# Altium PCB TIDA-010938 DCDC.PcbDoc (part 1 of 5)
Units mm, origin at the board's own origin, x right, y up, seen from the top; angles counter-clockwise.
Board outline 275 x 165 mm, 4 copper layers (Top Layer, Layer 1, Layer 2, Bottom Layer), stack 1.787 mm thick; 436 components, 216 nets, 1367 pads, 1992 vias.
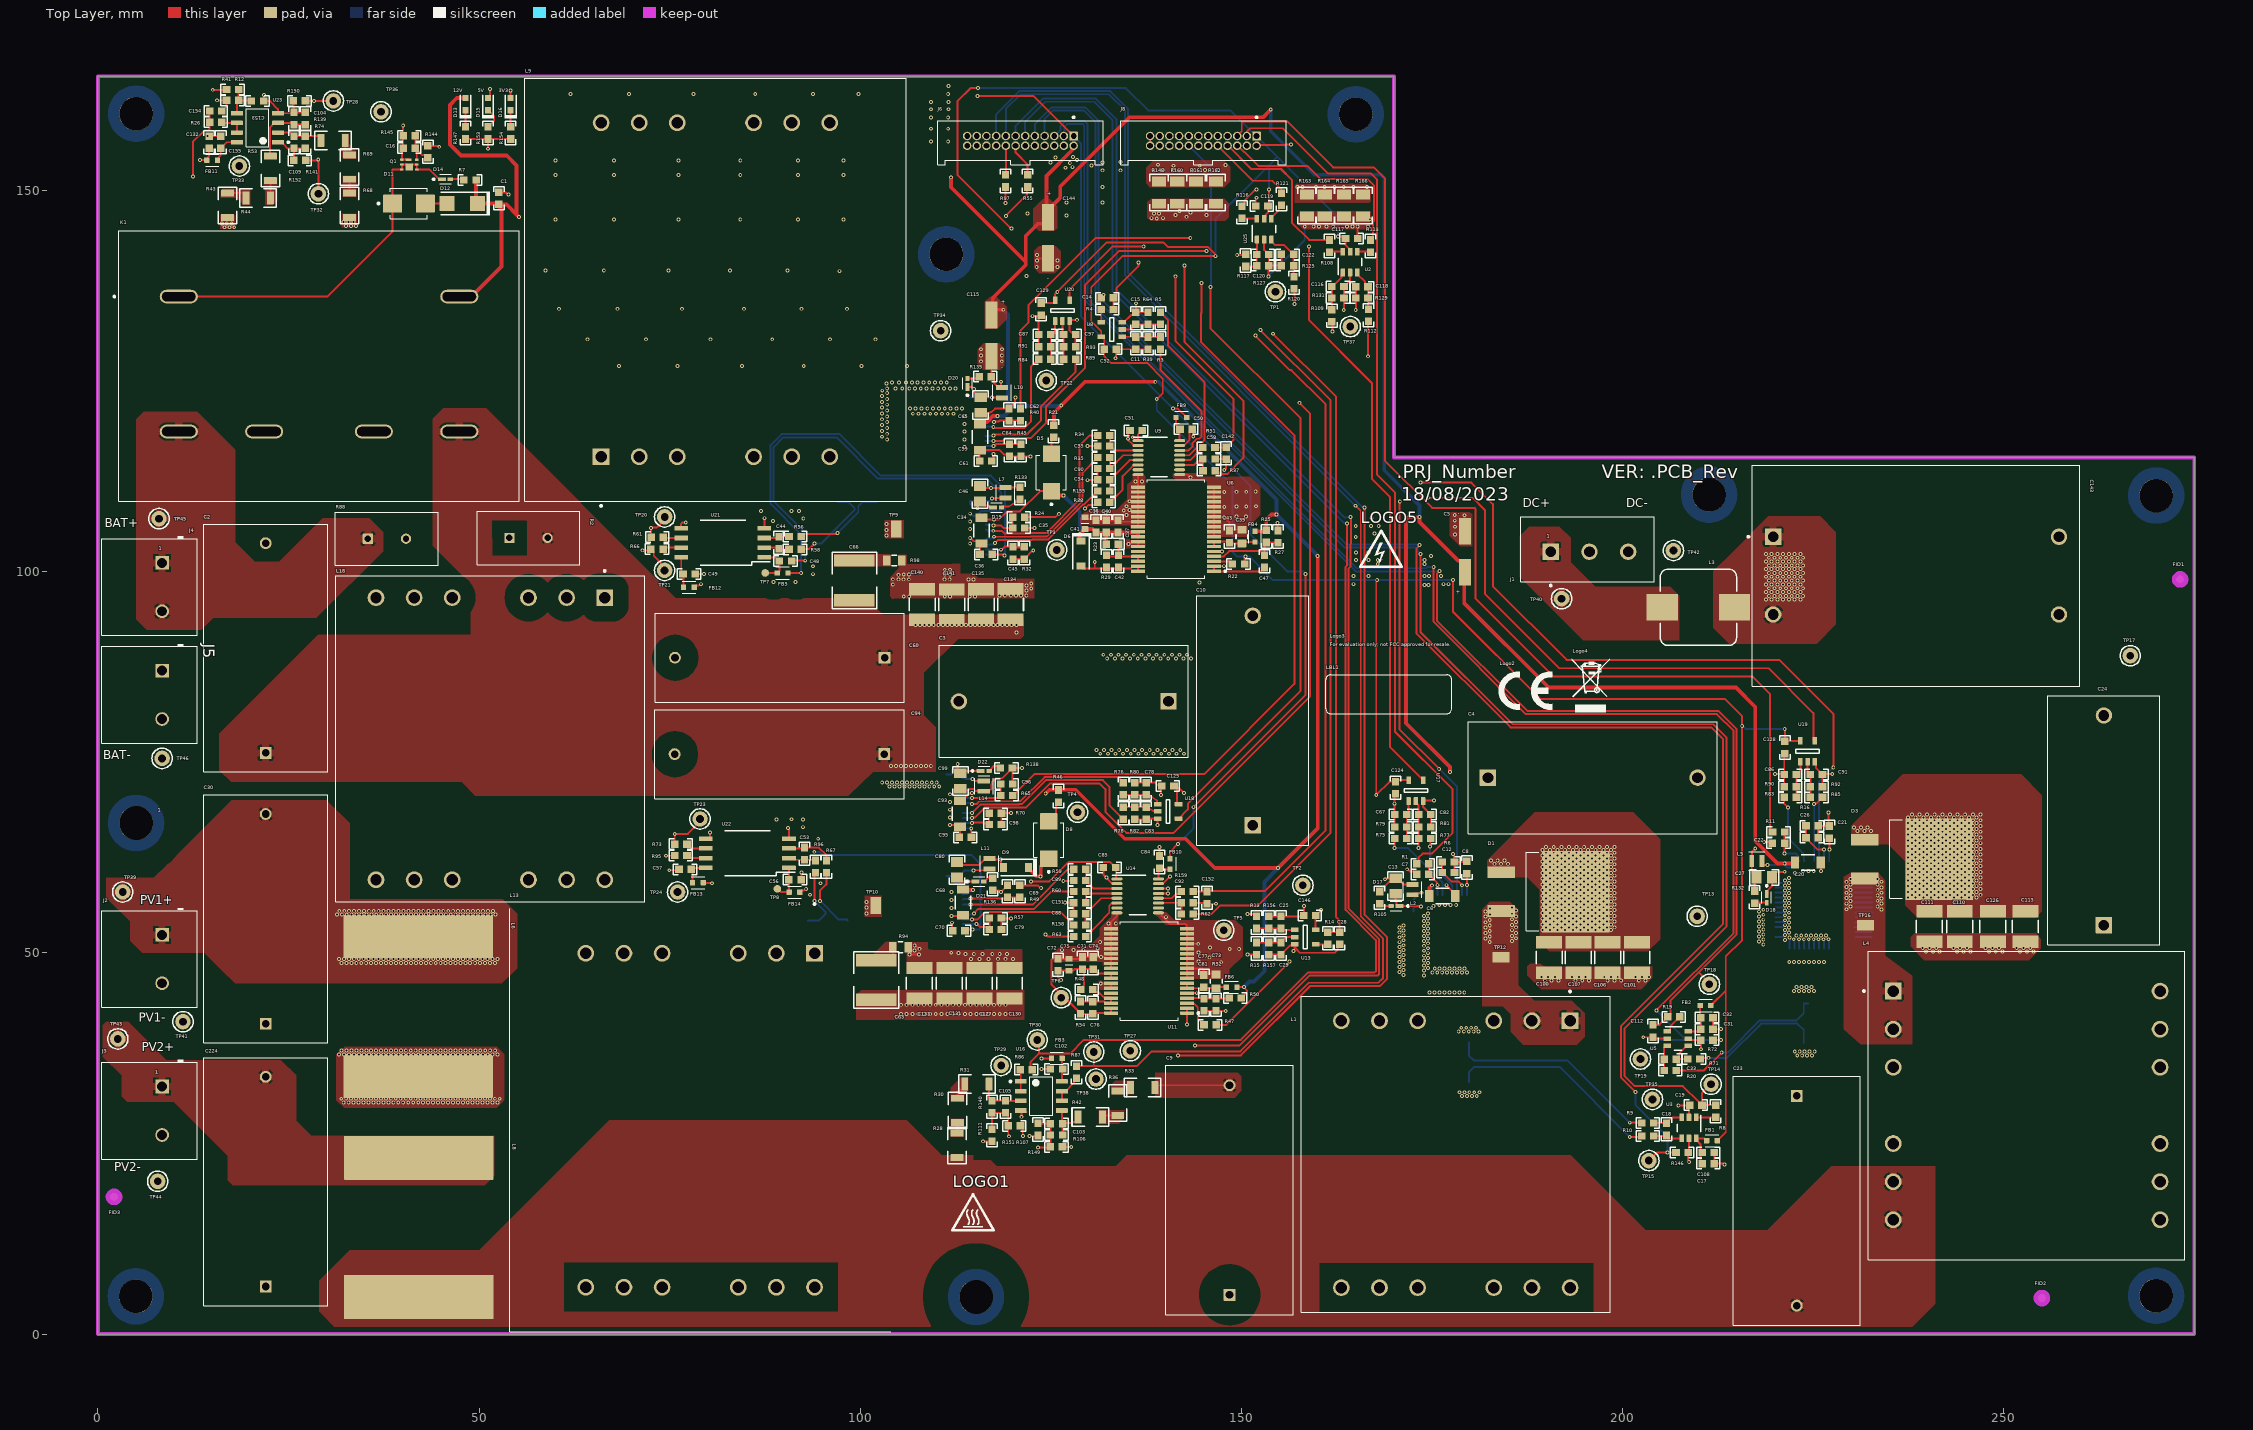
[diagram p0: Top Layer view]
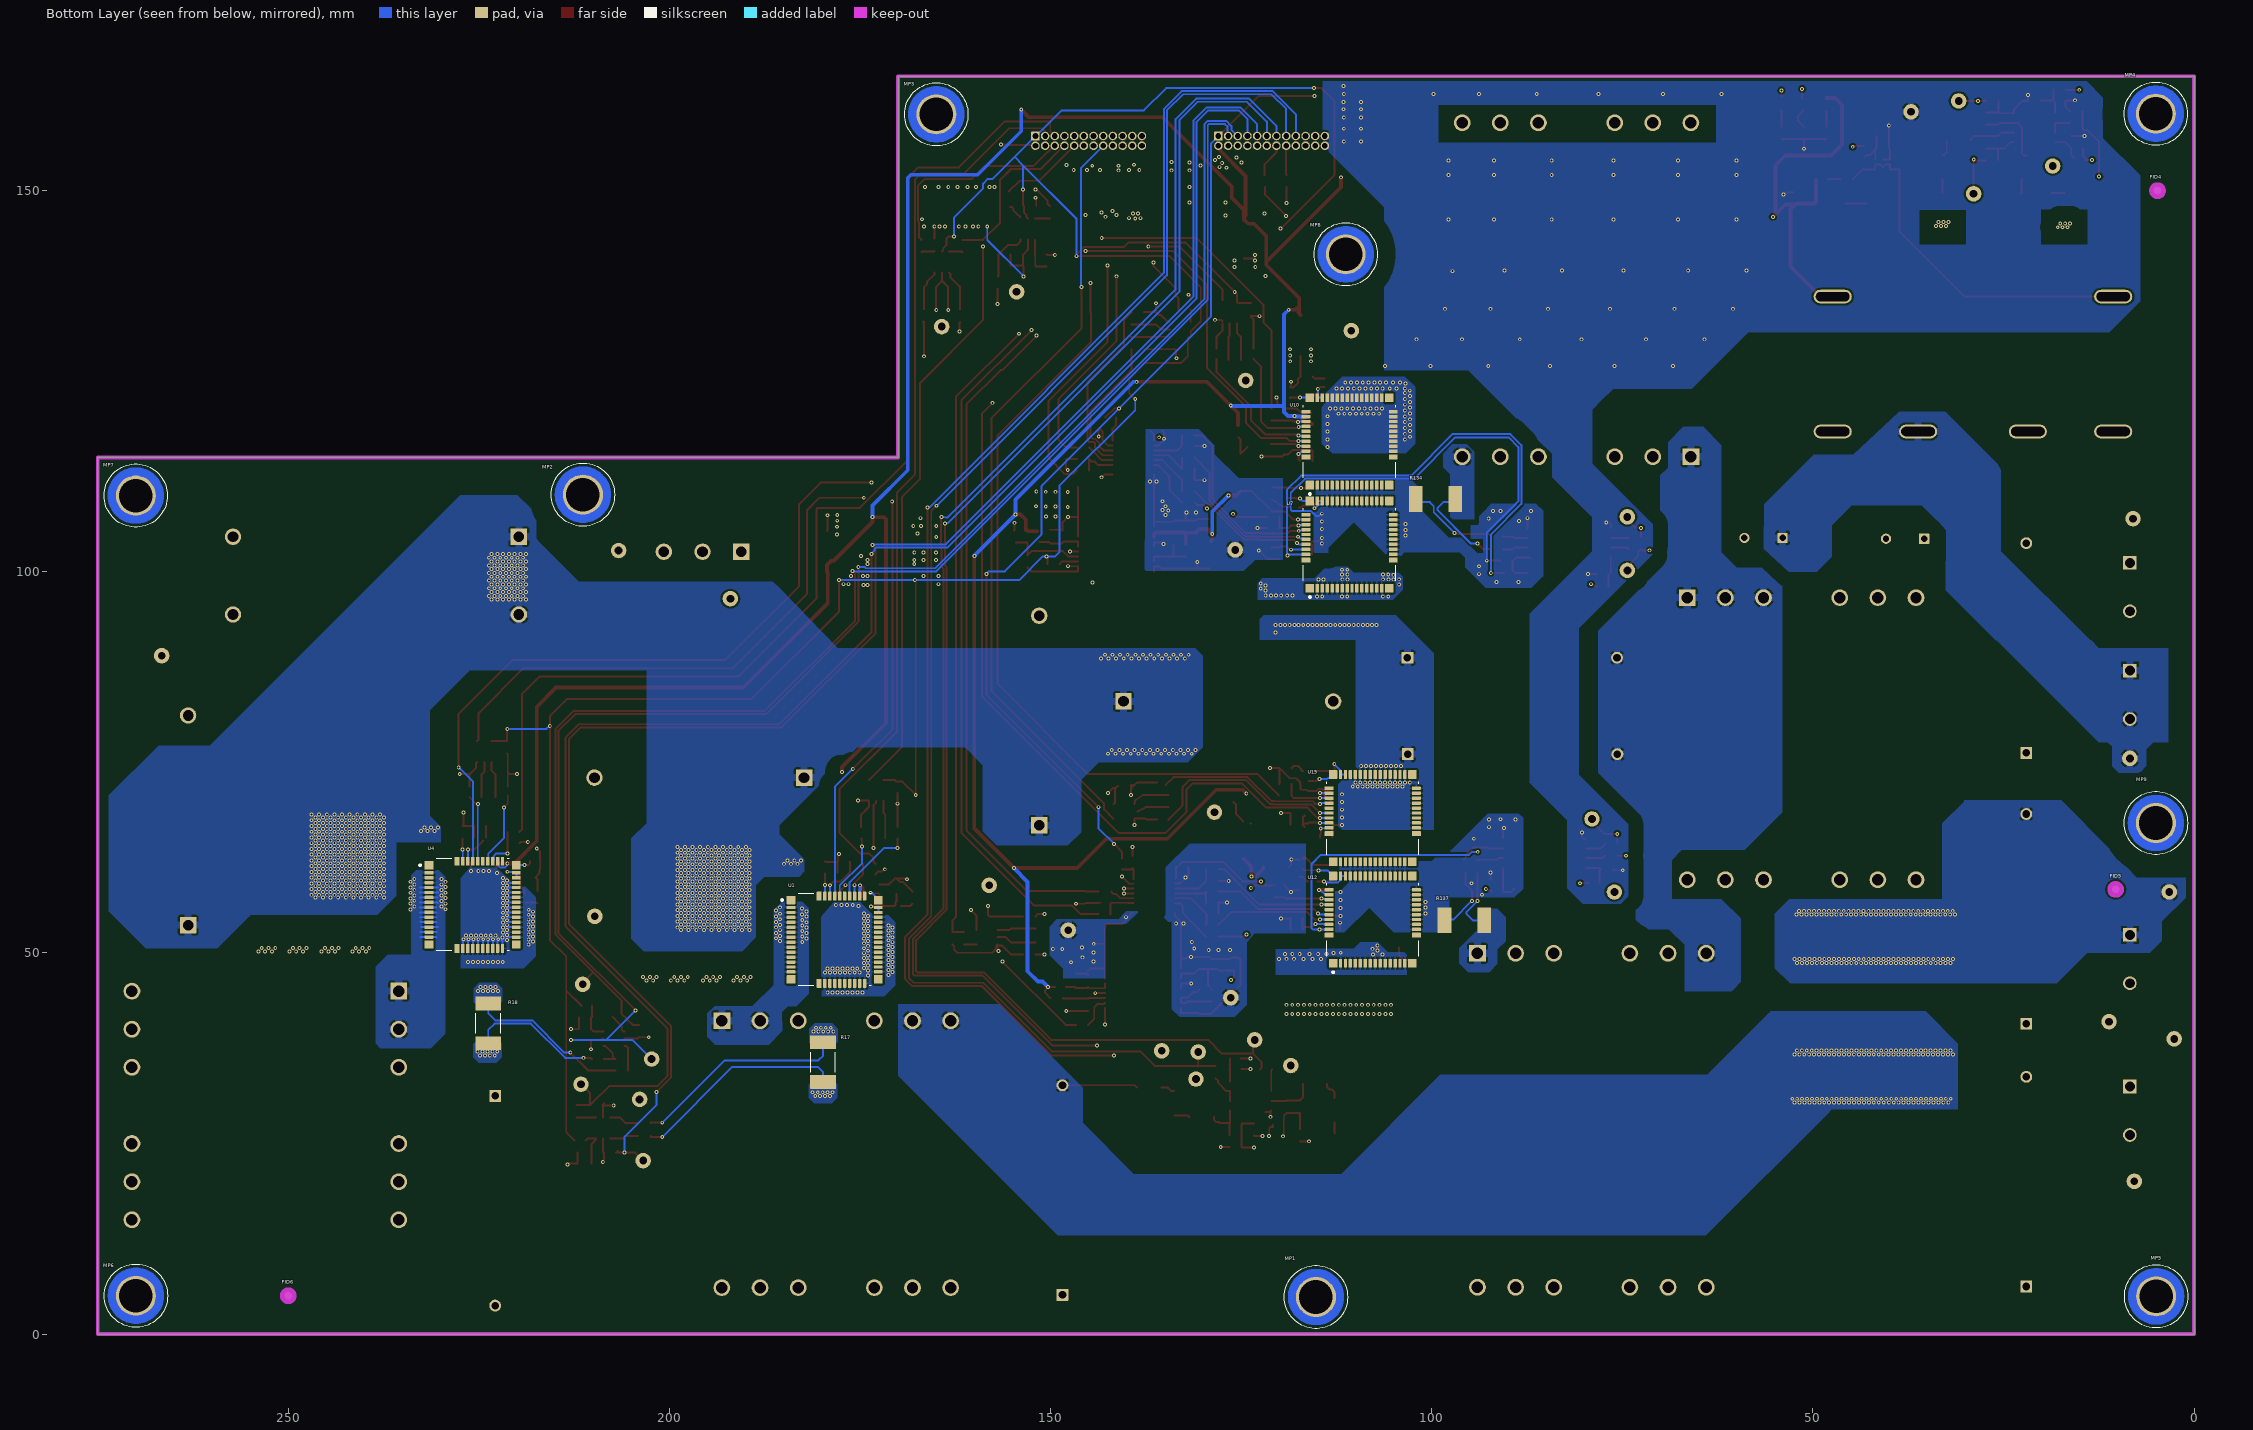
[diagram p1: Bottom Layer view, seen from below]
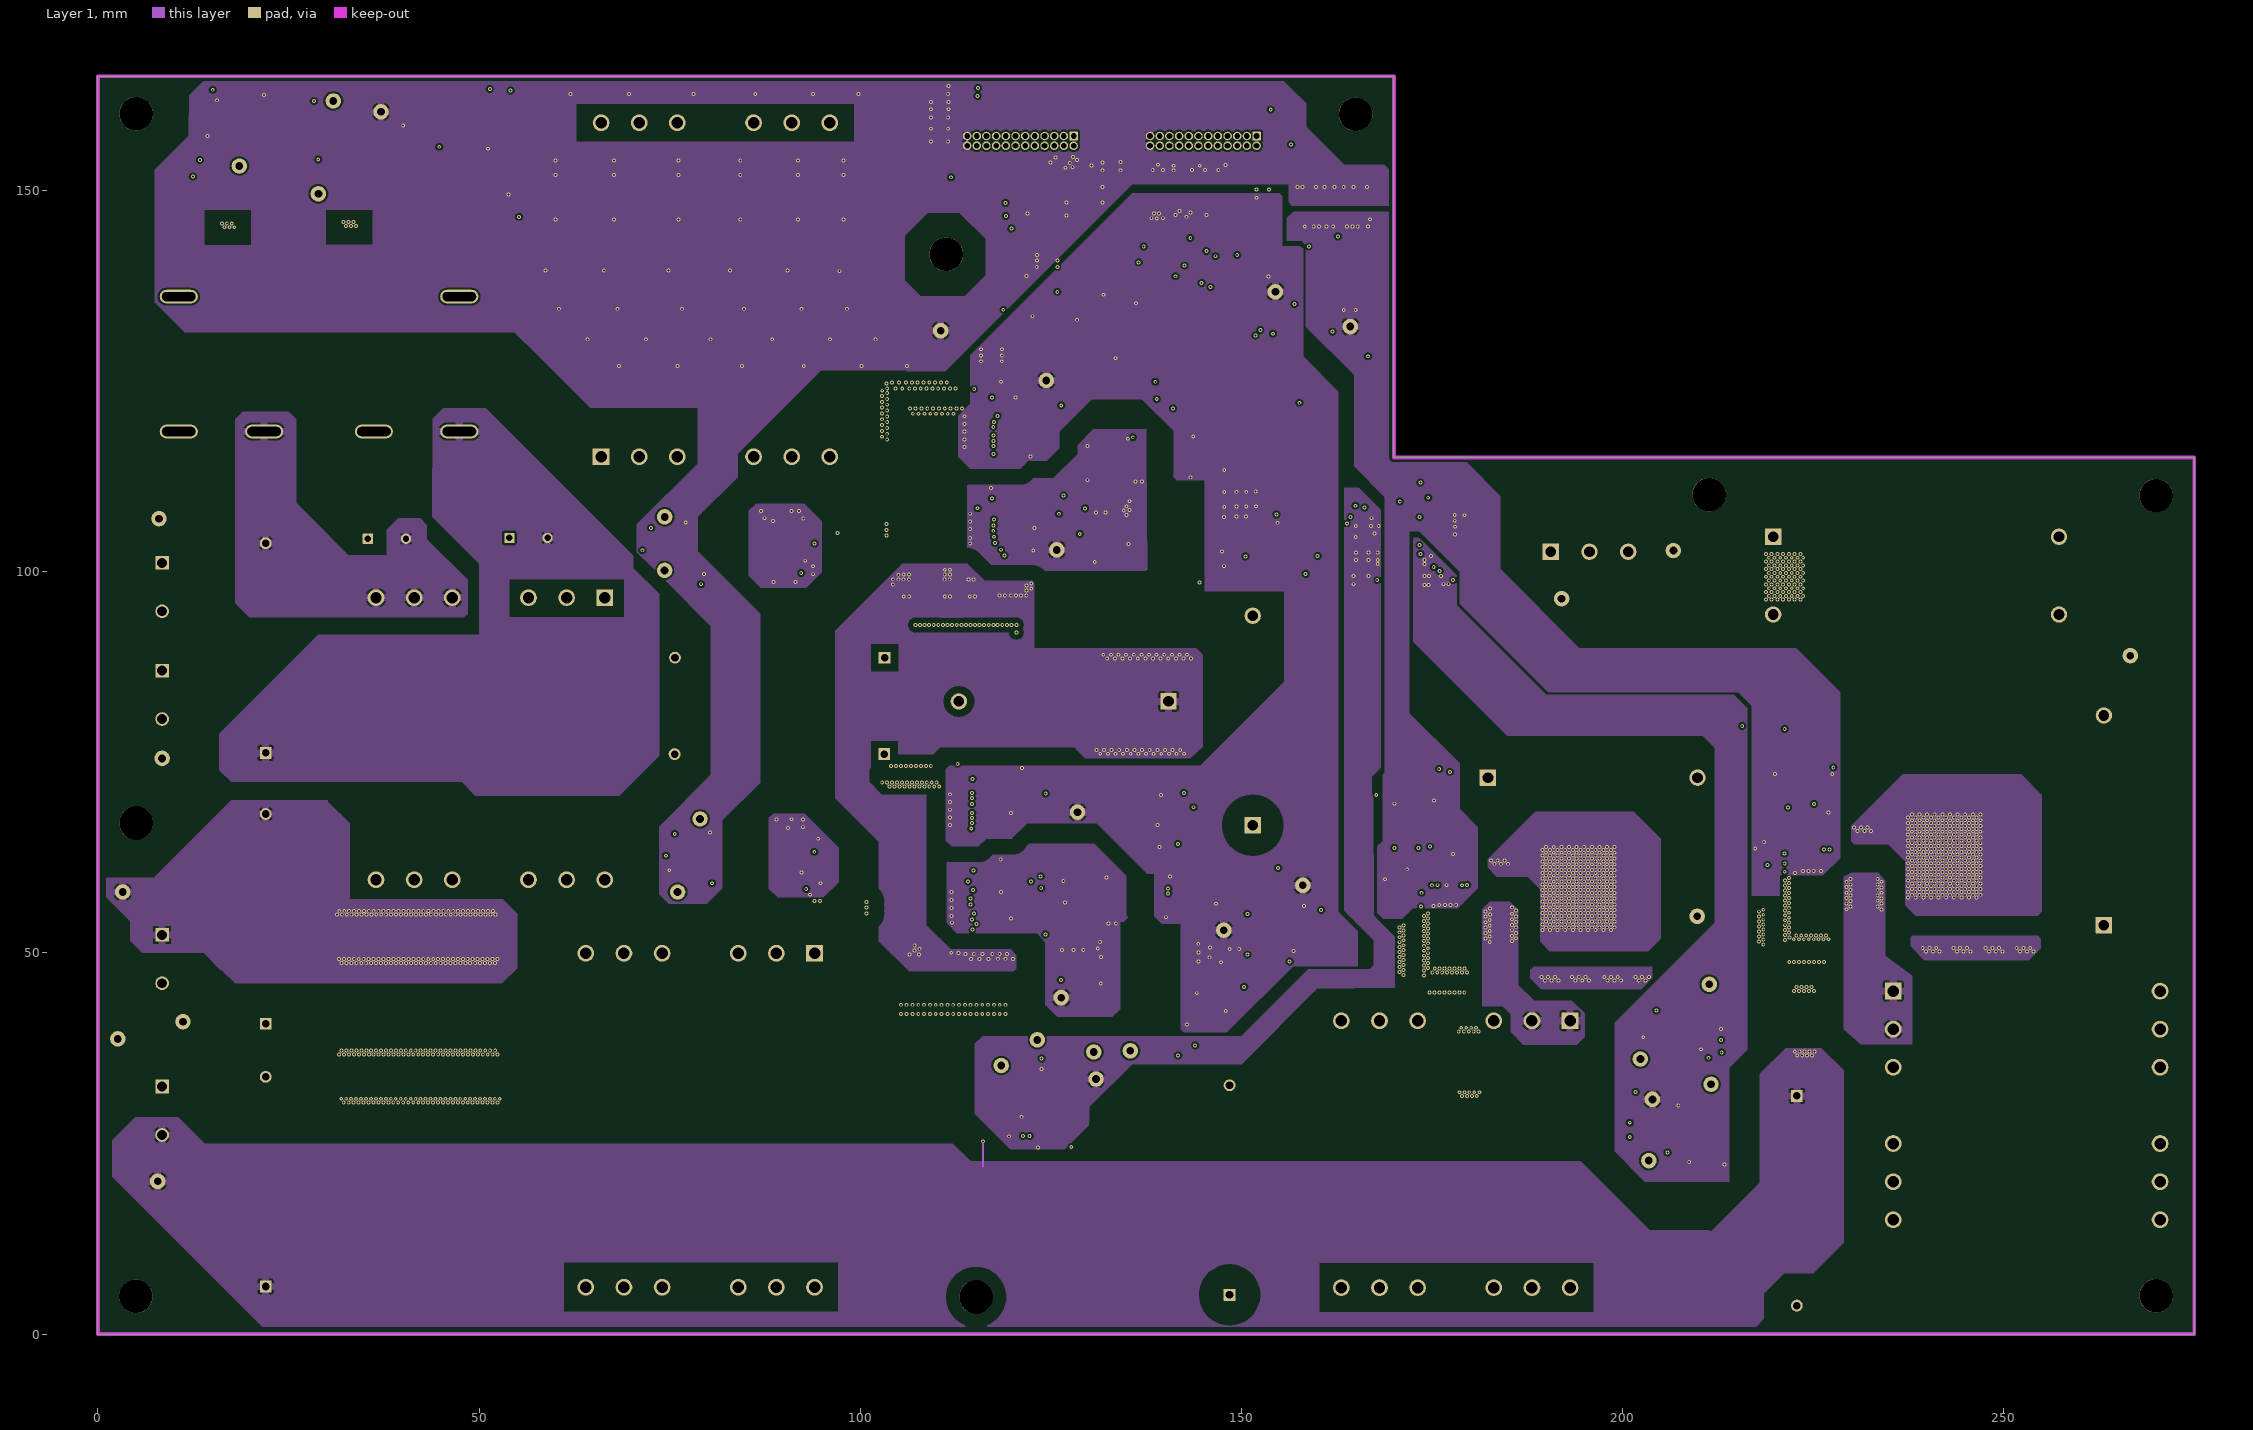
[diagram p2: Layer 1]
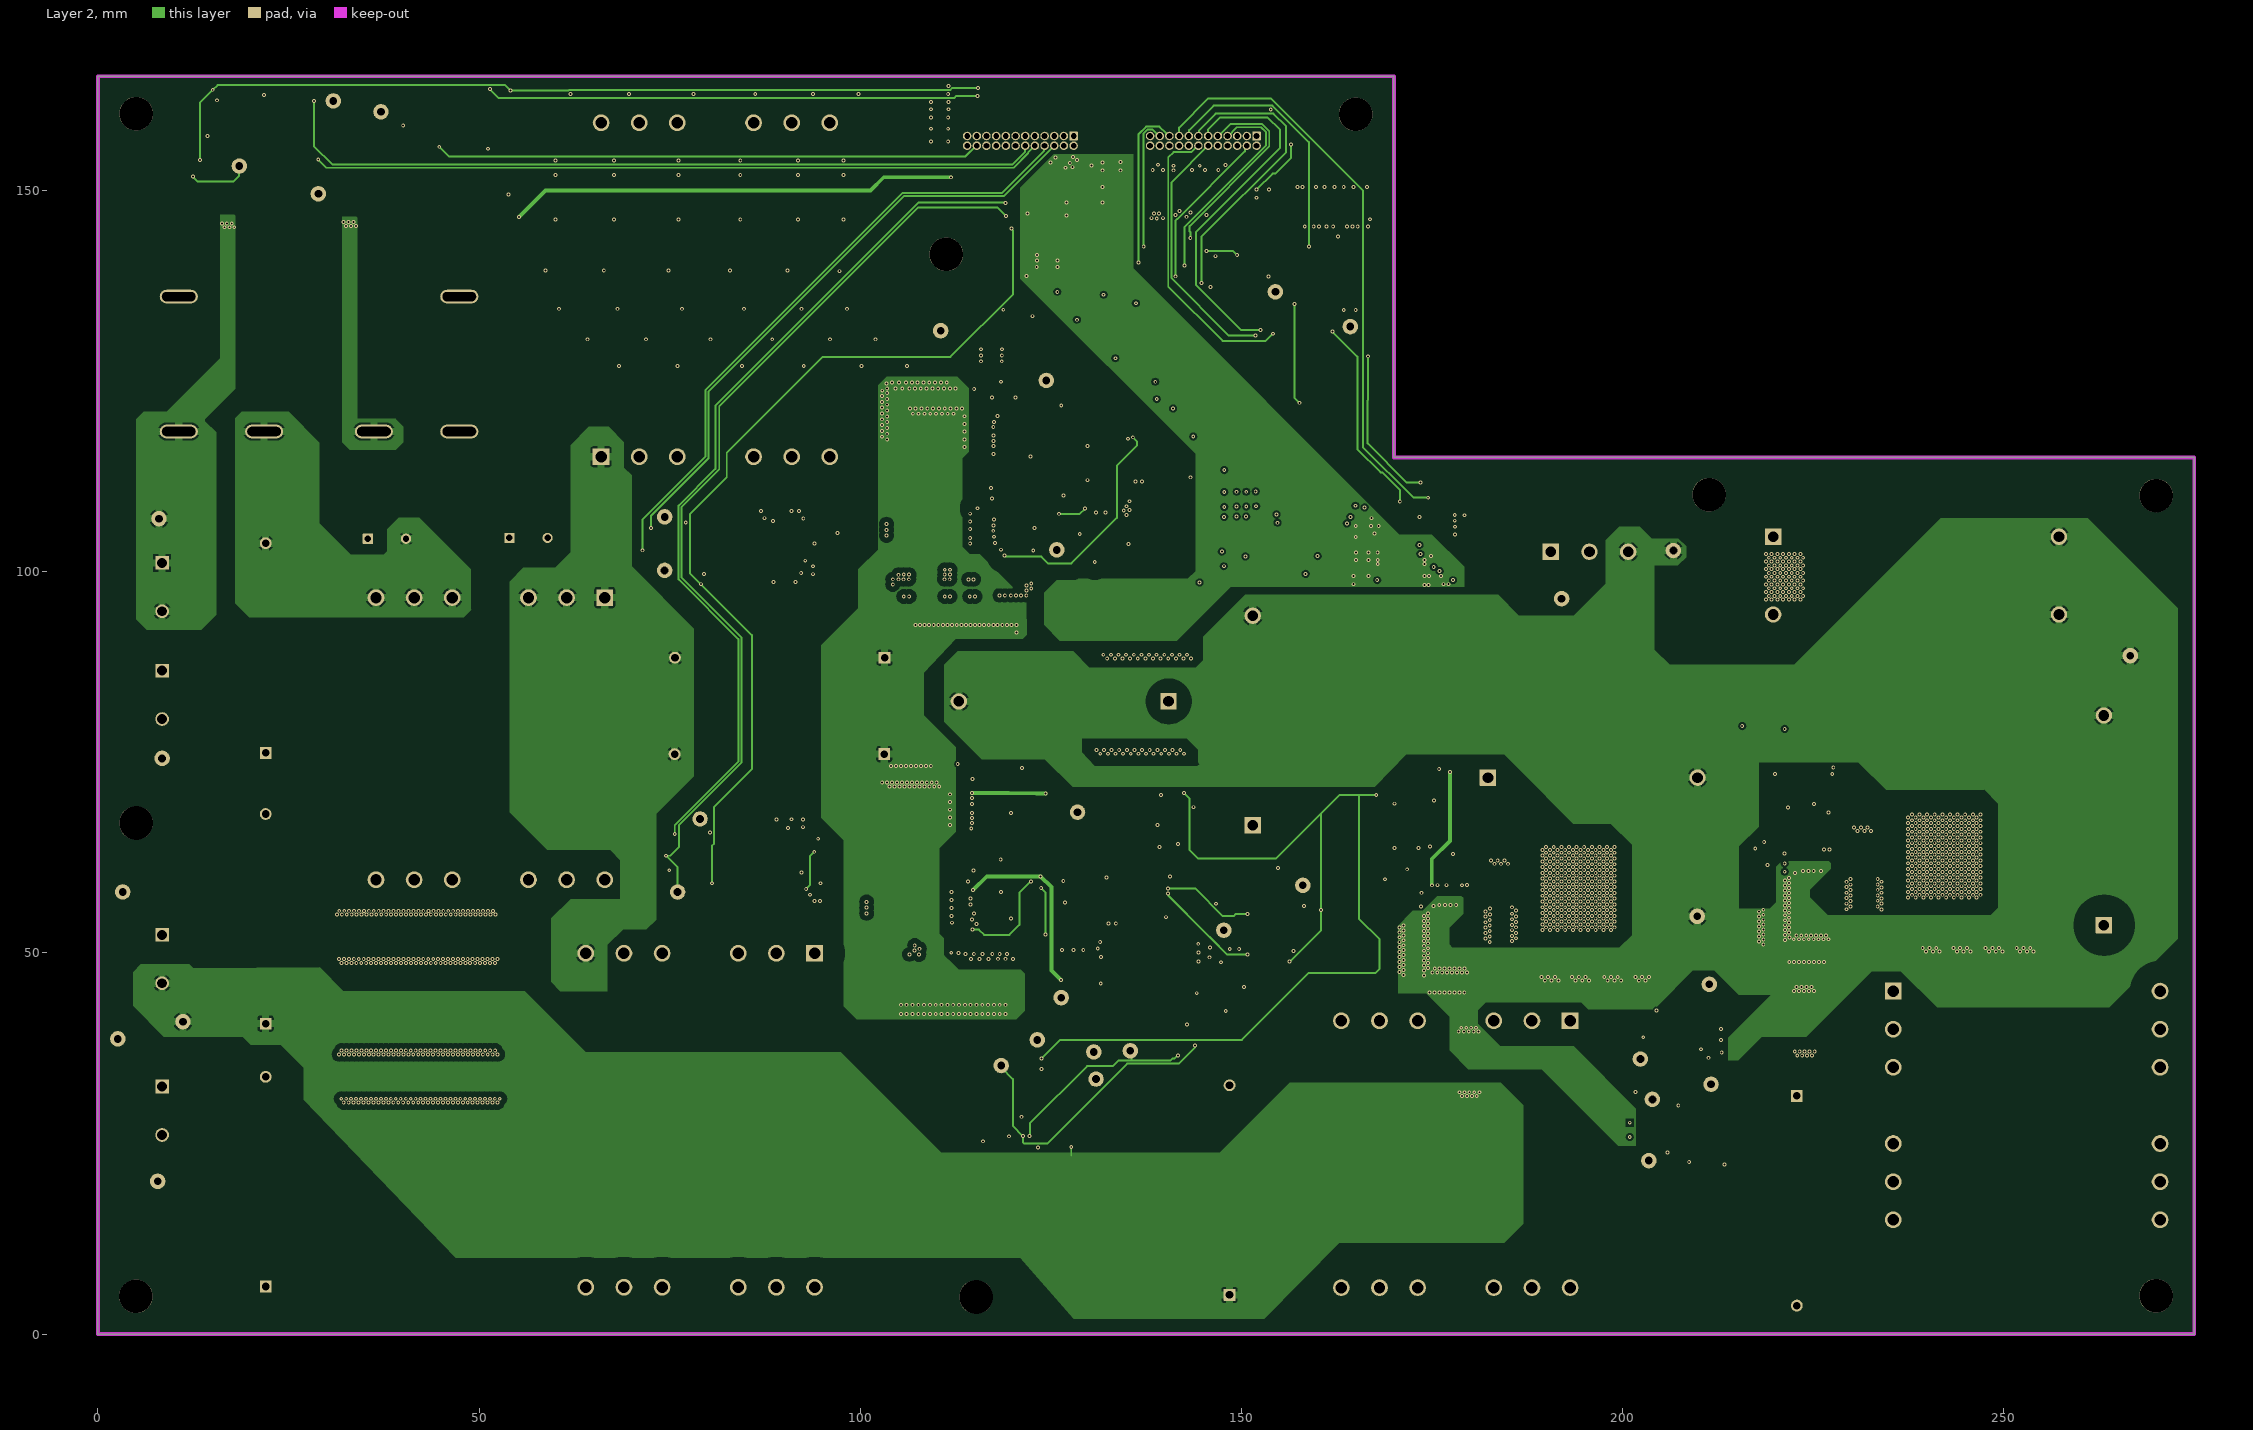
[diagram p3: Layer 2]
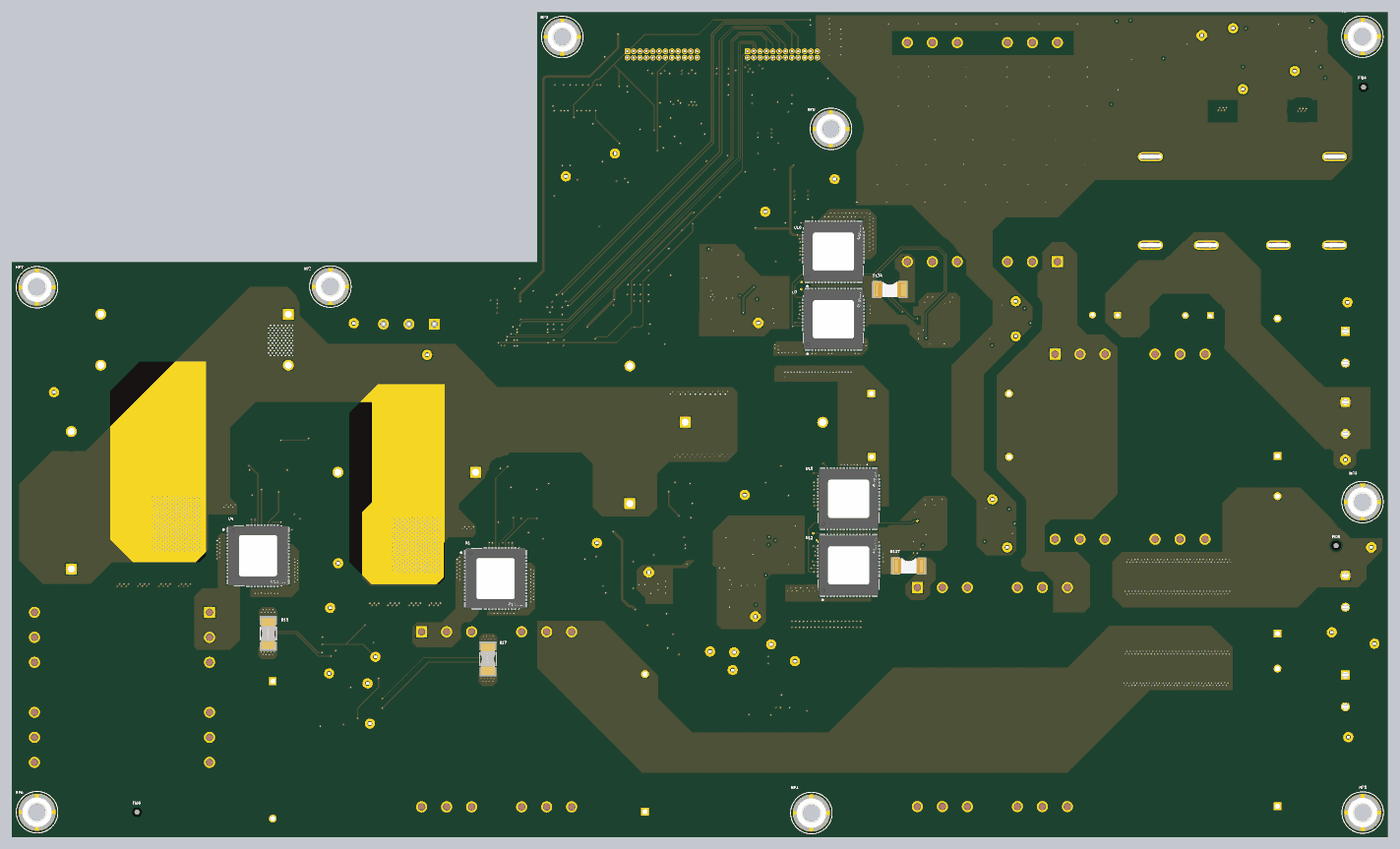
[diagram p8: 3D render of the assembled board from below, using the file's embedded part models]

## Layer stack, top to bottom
Top Solder: solder mask 0.0102, Solder Resist, Dk 3.5
Top Layer: signal copper 0.0356
Dielectric 1: prepreg 0.0711, PP-006, Dk 4.1
Layer 1: signal copper 0.035
Dielectric1: core 1.5037, FR-4 High Tg, Dk 4.8
Layer 2: signal copper 0.035
Dielectric 2: prepreg 0.0711, PP-006, Dk 4.1
Bottom Layer: signal copper 0.0356
Bottom Solder: solder mask 0.0102, Solder Resist, Dk 3.5

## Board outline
275,0 275,115 170,115 170,165 0,165 0,0

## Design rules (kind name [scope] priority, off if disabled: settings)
AcuteAngle [All] p1: minimum=4.50000000000000E+0001 checktracksonly=FALSE
AssemblyTestPointUsage [All] p1: valid=2
BoardOutlineClearance BoardOutlineClearance_MountingHoles [OnCopper and InComponentClass('Mounting Holes')] p1: gap=1 ignorepadtopadclearanceinfootprint=FALSE
BoardOutlineClearance BoardOutlineClearance_Poly [OnCopper and IsPoly] p2: gap=0.635 ignorepadtopadclearanceinfootprint=FALSE
BoardOutlineClearance [OnCopper and Not InComponentClass('Logo') and not InComponentClass('FiducialMark') and not InRegion(1000,500,4000,800) and not InPoly] p3: gap=1.016 ignorepadtopadclearanceinfootprint=FALSE
Clearance "Clearance Top HVN-HVP2" [InNetClass('HVN') vs (InNetClass('HVP') or InNetClass('Boost1p') or  InNetClass('Boost2p') or InNetClass('BatP') ) and (OnLayer('Top Layer') OR OnLayer('Bottom Layer'))] p1: gap=2 ignorepadtopadclearanceinfootprint=TRUE
Clearance "Clearance Top HVN-HVP" [InNetClass('HVN') AND (OnLayer('Top Layer') OR OnLayer('Bottom Layer')) vs (InNetClass('HVP') or InNetClass('Boost1p') or  InNetClass('Boost2p') or InNetClass('BatP') )] p2: gap=2 ignorepadtopadclearanceinfootprint=TRUE
Clearance GaN_SW [(InNamedPolygon('Layer 2-Bat_IN-')) vs (InNet('SW1') OR InNet('SW2'))] p3: gap=0.7 ignorepadtopadclearanceinfootprint=TRUE
Clearance SW_Bidirect1 [InNetClass('HV_SW_BAT1') vs InNetClass('HVN') or  InNetClass('HVP')] p4: gap=2.1 ignorepadtopadclearanceinfootprint=TRUE
Clearance SW_Bidirect2 [InNetClass('HV_SW_BAT2') vs InNetClass('HVN') or InNetClass('HVP')] p5: gap=2.1 ignorepadtopadclearanceinfootprint=TRUE
Clearance HVN_HVP_GAN [(InNamedPolygon('layer 2-Bat_IN-') AND InNetClass('HVN')) vs (InNamedPolygon('TOP_LAYER_DC_BUS+_P028') AND InNetClass('HVP'))] p6: gap=0.7 ignorepadtopadclearanceinfootprint=TRUE
Clearance HVN_HVP [InNetClass('HVN') vs InNetClass('HVP') or InNetClass('Boost1p') or  InNetClass('Boost2p') or InNetClass('BatP')] p7: gap=0.7 ignorepadtopadclearanceinfootprint=TRUE
Clearance Clearance_Keepouts [((IsTrack Or IsArc) And Not InPoly) And IsFree and IsKeepOut vs ((IsTrack Or IsArc) And Not InPoly) And IsFree and IsKeepOut] p8: gap=0 ignorepadtopadclearanceinfootprint=FALSE
Clearance Clearance_Poly [InPolygon] p9: gap=0.254 ignorepadtopadclearanceinfootprint=TRUE
Clearance Clearance_FiducialMark [IsKeepOut and InComponentClass('FiducialMark') vs IsPad and InComponentClass('FiducialMark')] p10: gap=0 ignorepadtopadclearanceinfootprint=TRUE
Clearance "Minimum distance" [All] p11: gap=0.15 ignorepadtopadclearanceinfootprint=TRUE
ComponentClearance ComponentClearance_MountingHoles_FiducialMarks [InComponentClass('Mounting Holes') vs InComponentClass('FiducialMark')] p1: gap=1.27 collisioncheckmode=3 verticalgap=0.254 showdistances=FALSE
ComponentClearance ComponentClearance_Shunt [InComponentClass('Header') vs InComponentClass('Shunt')] p2: gap=0 collisioncheckmode=3 verticalgap=0 showdistances=FALSE
ComponentClearance ComponentClearance_Logo [InComponentClass('Logo')] p3: gap=0.762 collisioncheckmode=3 verticalgap=0.254 showdistances=FALSE
ComponentClearance ComponentClearance_ScrewToNut [(HasFootprint('NY PMS 440 0025 PH')) vs (HasFootprint('Keystone_1902C'))] p4: gap=0.127 collisioncheckmode=3 verticalgap=0.254 showdistances=FALSE
ComponentClearance ComponentClearance_MountingHoles [InComponentClass('Mounting Holes')] p5: gap=2.54 collisioncheckmode=3 verticalgap=2540 showdistances=FALSE
ComponentClearance ComponentClearance_SmallPassives [HasFootprint('0201*') or HasFootprint('0402*') or HasFootprint('0508') or HasFootprint('0603*') or HasFootprint('0612') or HasFootprint('0805*') or HasFootprint('0815*') or HasFootprint('0830*') or HasFootprint('1206*') or HasFootprint('1210*') or HasFootprint('1808*') or HasFootprint('1812*') or HasFootprint('1825*') or HasFootprint('2010*') or HasFootprint('2220*') or HasFootprint('2225*') or HasFootprint('2512*') or HasFootprint('2728*') or HasFootprint('3518*') vs HasFootprint('0201*') or HasFootprint('0402*') or HasFootprint('0508') or HasFootprint('0603*') or HasFootprint('0612') or HasFootprint('0805*') or HasFootprint('0815*') or HasFootprint('0830*') or HasFootprint('1206*') or HasFootprint('1210*') or HasFootprint('1808*') or HasFootprint('1812*') or HasFootprint('1825*') or HasFootprint('2010*') or HasFootprint('2220*') or HasFootprint('2225*') or HasFootprint('2512*') or HasFootprint('2728*') or HasFootprint('3518*')] p6: gap=0.38 collisioncheckmode=3 verticalgap=0.254 showdistances=FALSE
ComponentClearance ComponentClearance_THtoSMT [IsThruComponent vs IsSMTComponent] p7: gap=0.762 collisioncheckmode=3 verticalgap=0.762 showdistances=FALSE
ComponentClearance ComponentClearance_THtoTH [IsThruComponent vs IsThruComponent] p8: gap=0.508 collisioncheckmode=3 verticalgap=0.762 showdistances=FALSE
ComponentClearance [All] p9: gap=0.508 collisioncheckmode=3 verticalgap=0.254 showdistances=FALSE
DiffPairsRouting [All] p1: maxlimit=2.54 minlimit=0.254 mostfreqgap=0.254 toplayer_minwidth=0.381 toplayer_maxwidth=0.381 toplayer_prefwidth=0.381 midlayer1_minwidth=0.381 midlayer1_maxwidth=0.381 midlayer1_prefwidth=0.381 midlayer2_minwidth=0.381 midlayer2_maxwidth=0.381 midlayer2_prefwidth=0.381 bottomlayer_minwidth=0.381 bottomlayer_maxwidth=0.381 bottomlayer_prefwidth=0.381 maxuncoupledlength=25.4
FabricationTestPointUsage TestPointUsage [All] p1: valid=2 allowmultiple=FALSE
FabricationTestpoint Testpoint [All] p1: side=3 testpointundercomponent=TRUE minsize=1.016 maxsize=2.54 preferedsize=1.524 minholesize=0 maxholesize=1.016 preferedholesize=0.813 testpointgrid=0.025 allowsidetop=TRUE allowsidebottom=TRUE usegrid=TRUE gridtolerance=0
FanoutControl Fanout_LCC [IsLCC] p1: bgadir=Out bgaviamode=Centered fanoutstyle=Auto fanoutdirection=Alternating viagrid=0.025 // Fanout_LCC (Default Rule)
FanoutControl Fanout_BGA [IsBGA] p2: bgadir=Out bgaviamode=Centered fanoutstyle=Auto fanoutdirection=Alternating viagrid=0.025 // Fanout_BGA (Default Rule)
FanoutControl Fanout_Default [All] p4: bgadir=Out bgaviamode=Centered fanoutstyle=Auto fanoutdirection=Alternating viagrid=0.025 // Fanout_Default (Default Rule)
FanoutControl Fanout_Small [(CompPinCount < 5)] p5: bgadir=Out bgaviamode=Centered fanoutstyle=Auto fanoutdirection=OutThenIn viagrid=0.025 // Fanout_Small (Default Rule)
HoleSize [All] p1: absolutevalues=TRUE maxlimit=6.375 minlimit=0.2 maxpercent=80.000 minpercent=20.000
MinimumAnnularRing MinimumAnnularRing_ThermalPadVias [IsVia and InAnyComponent] p1: minimumring=0.15
MinimumAnnularRing [All] p2: minimumring=0.125
MinimumSolderMaskSliver MinimumSolderMaskSliver_Logo [InComponentClass('Logo') vs InComponentClass('Logo')] p1: minsoldermaskwidth=0.018
MinimumSolderMaskSliver [All] p2: minsoldermaskwidth=0.1
PlaneConnect [All] p1: planeconnectstyle=Relief reliefexpansion=0.254 reliefentries=4 reliefconductorwidth=0.254 reliefairgap=0.254
PolygonConnect "GaN 1" [IsNamedPolygon('BOTTOM_LAYER_BAT_IN-_P103') or    IsNamedPolygon('BOTTOM_LAYER_BAT_IN-_P061')  or IsNamedPolygon('BOTTOM_LAYER_DC_BUS+_P120')    or IsNamedPolygon('Bottom Layer-NetD1_2')   or IsNamedPolygon('Bottom Layer-NetD3_2')   or IsNamedPolygon('BOTTOM_LAYER_DC_BUS-_P046') or IsNamedPolygon('BOTTOM_LAYER_BAT_IN-_P061') or IsNamedPolygon('BOTTOM_LAYER_DC_BUS+_P027') or IsNamedPolygon('gan1_sw') or IsNamedPolygon('gan2_sw')      or IsNamedPolygon('BOTTOM_LAYER_DC_BUS-_P045') or IsNamedPolygon('BOTTOM_LAYER_GND_BAT_P061') or  IsNamedPolygon('Bottom_Layer-Bat_IN-') vs HasFootprint('RQS0052C-C01-MFG')] p1: thpad.connectstyle=Direct thpad.reliefconductorwidth=1 thpad.reliefentries=4 thpad.polygonreliefangle="90 Angle" thpad.airgapwidth=0.254 smdpad.connectstyle=Relief smdpad.reliefconductorwidth=0.254 smdpad.reliefentries=4 smdpad.polygonreliefangle="90 Angle" smdpad.airgapwidth=0.254 via.connectstyle=Direct via.reliefconductorwidth=0.254 via.reliefentries=4 via.polygonreliefangle="90 Angle" via.airgapwidth=0.254
PolygonConnect PolygonConnect_1 [All] p2: thpad.connectstyle=Relief thpad.reliefconductorwidth=1 thpad.reliefentries=4 thpad.polygonreliefangle="90 Angle" thpad.airgapwidth=0.254 smdpad.connectstyle=Direct smdpad.reliefconductorwidth=0.254 smdpad.reliefentries=4 smdpad.polygonreliefangle="90 Angle" smdpad.airgapwidth=0.254 via.connectstyle=Direct via.reliefconductorwidth=0.254 via.reliefentries=4 via.polygonreliefangle="90 Angle" via.airgapwidth=0.254
RoutingVias ThermalPadVias [IsVia and InAnyComponent] p1: holewidth=0.254 width=0.508 viastyle="Through Hole" minholewidth=0.2 minwidth=0.5 maxholewidth=1.016 maxwidth=1.651
RoutingVias [All] p2: holewidth=0.406 width=0.864 viastyle="Through Hole" minholewidth=0.2 minwidth=0.61 maxholewidth=1.016 maxwidth=1.651
SilkToBoardRegionClearance [Not ((IsComment or IsDesignator) And (Hide <> 'False')) and not InRegion(1000,500,4000,800)] p1:
SilkToSilkClearance SilkToSilkClearance_Pb-FreeLogo [(HasFootprint('Pb-Free_Overlay_Medium') OR HasFootprint('Pb-Free_Overlay_Small')) vs (HasFootprint('Pb-Free_Overlay_Medium') OR HasFootprint('Pb-Free_Overlay_Small'))] p1: silktosilkclearance=0
SilkToSilkClearance [All] p2: silktosilkclearance=0.1
SilkToSolderMaskClearance SilkToComponentPadClearance [(IsPad or IsFill or IsRegion) and InAnycomponent] p1: minsilkscreentomaskgap=0.01 clearancetoexposedcopper=TRUE
SilkToSolderMaskClearance "Silk to Solder Mask Opening" [All] p2: minsilkscreentomaskgap=0.01 clearancetoexposedcopper=FALSE
SolderMaskExpansion [All] p1: expansion=0.05 istentingtop=FALSE
UnRoutedNet [All] p1: checkbadconnections=TRUE
Width Width12V [InNet('12V_HVN') or  InNet('12V_SW1') or InNet('12V_SW2')] p1: maxlimit=2.54 minlimit=0.25 preferedwidth=0.5
Width Width_1 [All] p2: maxlimit=0.254 minlimit=0.254 preferedwidth=0.254
14 further rules are at their usual default settings.

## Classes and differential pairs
component class Designator: !PCB FID1 FID2 FID3 FID4 FID5 FID6 LBL1 LOGO1 Logo2 Logo3 Logo4 LOGO5 MP1 MP2 MP3 MP4 MP5 MP6 MP7 MP8 MP9 ZZ1 ZZ2 ZZ3 ZZ4
component class Designator: C102 C103 C104 C105 C109 C132 C153 C154 C155 FB3 FB11 R12 R26 R28 R30 R31 R33 R36 R41 R42 R43 R44 R53 R68 R69 R74 R86 R87 R106 R107 R111 R139 R140 R141 R149 R150 R151 R152 TP27 TP28 TP29 TP30 TP31 TP32 TP33 U16 U23
component class Designator: C67 C78 C82 C83 C86 C87 C91 C97 C116 C117 C118 C119 C120 C122 C124 C125 C128 C129 R75 R76 R77 R78 R79 R80 R81 R82 R83 R84 R85 R89 R90 R91 R92 R93 R108 R109 R112 R113 R116 R117 R120 R121 R125 R127 R129 R131 U2 U17 U18 U19 U20 U25
component class Designator: C5 C6 C7 C8 C9 C10 C12 C13 C17 C18 C19 C30 C100 C101 C106 C107 C108 D1 D17 FB1 L1 L2 L6 R1 R6 R8 R9 R10 R17 R105 R146 TP12 TP13 TP14 TP15 U1 U3
component class Designator: C25 C28 C29 C53 C56 C57 C66 C68 C69 C70 C71 C72 C73 C74 C75 C76 C77 C79 C80 C81 C84 C85 C88 C89 C92 C93 C94 C95 C96 C98 C99 C134 C135 C140 C141 C146 C151 C152 D8 D9 D21 D22 FB6 FB10 FB13 FB14 L11 L13 L14 R13 R14 R15 R46 R47 R48 R49 R50 R52 R54 R57 R59 R60 R62 R63 R65 R67 R70 R73 R95 R96 R98 R136 R137 R138 R156 R157 R158 R159 TP4 TP5 TP6 TP8 TP10 TP23 TP24 U11 U12 U13 U14 U15 U22
component class Designator: C11 C14 C15 C34 C35 C36 C37 C38 C39 C40 C41 C42 C43 C44 C45 C46 C47 C48 C49 C50 C51 C52 C54 C55 C58 C59 C60 C61 C62 C63 C64 C65 C90 C115 C127 C130 C131 C133 C142 D5 D6 D19 D20 FB4 FB5 FB9 FB12 L7 L9 L10 R3 R4 R5 R21 R22 R23 R24 R25 R27 R29 R32 R34 R35 R37 R38 R39 R40 R45 R51 R56 R58 R61 R64 R66 R94 R133 R134 R135 R155 TP1 TP2 TP3 TP7 TP9 TP20 TP21 TP22 U6 U7 U8 U9 U10 U21
net class HVP: DC_Bus+ NetC63_1 NetC66_1
net class Boost2SW: NetD3_2
net class Boost2p: Boost2_IN+ "PV2 Bus+"
net class Boost1SW: NetD1_2
net class Boost1p: Boost1_IN+ "PV1 Bus+"
net class BatP: "BAT Bus+" BatIN+ NetC2_2
net class HV_SW_BAT2: 5V_SW2 12V_SW2 F\A\U\L\T\_Bat_H2_init IN_PWM_Bat_H2 NetC53_1 NetC53_2 NetC56_1 NetC69_2 NetC76_1 NetC79_2 NetC80_1 NetC88_2 NetC89_2 NetC151_2 NetD21_2 NetL11_2 NetL13_1 NetR63_1 NetU11_32 NetU12_17 NetU12_27 NetU12_43 NetU12_47 NetU12_52 NetU14_7 NetU15_1 NetU15_16 O\C\_Bat_H2_init SW2 TEMP_Bat_H2_init
net class HV_SW_BAT1: 5V_SW1 12V_SW1 F\A\U\L\T\_Bat_H1_init IN_PWM_Bat_H1 NetC35_2 NetC42_1 NetC44_1 NetC44_2 NetC45_2 NetC46_1 NetC48_1 NetC54_2 NetC55_2 NetC90_2 NetD19_2 NetL7_2 NetL9_6 NetR38_1 NetU6_32 NetU7_17 NetU7_27 NetU7_43 NetU7_47 NetU7_52 NetU9_7 NetU10_1 NetU10_16 O\C\_Bat_H1_init SW1 TEMP_Bat_H1_init
net class PE: NetMP1_1 NetMP2_1 NetMP3_1 NetMP4_1 NetMP5_1 NetMP6_1 NetMP7_1 NetMP8_1
component class Label: LBL1
component class FiducialMark: FID1 FID2 FID3 FID4 FID5 FID6
component class AssemblyNote: ZZ1 ZZ2 ZZ3 ZZ4
net class HVN: 1V65_HVN 3V3_HVN 5V_HVN 12V_HVN "BAT Bus-" Batt_H1_Buff Batt_H2_Buff Batt_L1_Buff Batt_L2_Buff Boost_S1_Buff Boost_S2_Buff CS_Bat2-sw+ CS_Bat2_sw- CS_Batt1+ CS_Batt1- CS_Batt2+ CS_Batt2- CS_Boost1+ CS_Boost1- CS_Boost2+ CS_Boost2- DC_Bus- Enable_Buffer_DCDC F\A\U\L\T\__Bat_H1_Buff F\A\U\L\T\_Bat_H2_Buff F\A\U\L\T\_Bat_L1_init F\A\U\L\T\_Bat_L2_init F\A\U\L\T\_Boost1_init F\A\U\L\T\_Boost2_init F\A\U\L\T\_O\C\_Batt_H1_Buff F\A\U\L\T\_O\C\_Batt_H2_Buff F\A\U\L\T\_O\C\_Batt_L1_Buff F\A\U\L\T\_O\C\_Batt_L2_Buff F\A\U\L\T\_O\C\_Boost1_Buff F\A\U\L\T\_O\C\_Boost2_Buff GND_HVN NetC7_2 NetC8_2 NetC11_2 NetC12_2 NetC13_1 NetC15_2 NetC16_2 NetC17_1 NetC18_1 NetC18_2 NetC21_2 NetC22_2 NetC25_2 NetC26_2 NetC27_1 NetC29_2 NetC31_2 NetC33_1 NetC33_2 NetC39_2 NetC47_2 NetC49_1 NetC50_1 NetC57_1 NetC58_2 NetC61_2 NetC62_2 NetC64_2 NetC65_1 NetC67_2 NetC73_2 NetC78_2 NetC81_2 NetC82_2 NetC83_2 NetC84_1 NetC86_2 NetC87_2 NetC91_2 NetC92_2 NetC95_2 NetC96_2 NetC97_2 NetC98_2 NetC99_1 NetC102_2 NetC105_2 NetC116_2 NetC118_2 NetC120_2 NetC122_2 NetC153_2 NetD11_2 NetD13_1 NetD14_2 NetD15_1 NetD16_1 NetD17_2 NetD18_2 NetD20_2 NetD22_2 NetL2_2 NetL5_2 NetL10_2 NetL14_2 NetR4_1 NetR8_1 NetR14_1 NetR19_1 NetR22_2 NetR26_1 NetR47_2 NetR51_2 NetR61_2 NetR66_2 NetR73_2 NetR86_1 NetR95_2 NetR108_1 NetR113_1 NetR116_1 NetR121_1 NetR159_2 O\C\__Bat_H1_Buff O\C\_Bat_H2_Buff O\C\_Bat_L1_init O\C\_Bat_L2_init O\C\_Boost1_init O\C\_Boost2_init "PV1 Bus-" "PV2 Bus-" RY_DCPreCharge SN_DCPreCharge TEMP_Bat_L1_init TEMP_Bat_L2_init TEMP_Batt_H1_Buff TEMP_Batt_H2_Buff TEMP_Batt_L1_Buff TEMP_Batt_L2_Buff TEMP_Boost1_Buff TEMP_Boost1_init TEMP_Boost2_Buff TEMP_Boost2_init VS_Batt1+ VS_Batt1- VS_Boost1+ VS_Boost1- VS_Boost2+ VS_Boost2-
component class Designator: C1 C2 C3 C4 C16 C143 C144 D11 D12 D13 D14 D15 D16 J1 J2 J3 J4 J5 J6 J8 K1 L3 L18 Q1 R2 R7 R55 R88 R97 R144 R145 R147 R148 R153 R154 R160 R161 R162 R163 R164 R165 R166 TP34 TP35 TP36 TP37 TP38 TP39 TP40 TP41 TP42 TP43 TP44 TP45 TP46
component class Designator: C20 C21 C22 C23 C24 C26 C27 C31 C32 C33 C110 C111 C112 C113 C126 C224 D3 D18 FB2 L4 L5 L8 R11 R16 R18 R19 R20 R71 R72 R132 TP16 TP17 TP18 TP19 U4 U5

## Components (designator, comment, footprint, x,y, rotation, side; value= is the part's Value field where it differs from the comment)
C1 "GRM188R72A104KA35J" 0603 52.589,149 r90 top value=0.1uF
C2 "R533R456050P0M" FP-R533R456050P0M_RADIAL-MFG 22,90 r90 top locked value=5.6µF
C3 "C4AKOBU4270A3YJ" FP-C4AKOBU4270A3YJ_RADIAL-MFG 126.683,83 r180 top locked value=2.7µF
C4 "C4AKOBU4270A3YJ" FP-C4AKOBU4270A3YJ_RADIAL-MFG 196.085,73 r0 top locked value=2.7µF
C5 "UWT1E101MCL1GS" UWT_630x770 179.34,102.639 r90 top value=100uF
C6 "TMK316AB7106KLHT" 1206_180 176.361,57.459 r0 top value=10uF
C7 "GRM188R71H221KA01D" 0603 173.776,60.312 r0 top value=220pF
C8 "06033C104JAT2A" 0603 179.567,61.215 r270 top value=0.1uF
C9 "C4AUJBU4600M18J" FP-C4AUJBU4600M18J_RADIAL-MFG 148.439,18.894 r90 top locked value=6µF
C10 "C4AKOBU4270A3YJ" FP-C4AKOBU4270A3YJ_RADIAL-MFG 151.479,80.488 r90 top locked value=2.7µF
C11 "GRM188R71H221KA01D" 0603 136.143,129.998 r90 top value=220pF
C12 "GRM188R71H221KA01D" 0603 177.151,60.568 r180 top value=220pF
C13 "CGA4J3X7R1E225K125AB" 0805_HV 170.237,58.784 r90 top value=2.2uF
C14 "GRM188R71H221KA01D" 0603 132.411,135.936 r0 top value=220pF
C15 "GRM188R71H221KA01D" 0603 136.141,133.26 r270 top value=220pF
C16 "GRM188R71H221KA01D" 0603 40.844,155.566 r0 top value=220pF
C17 "TMK107BJ105KA-T" 0603 211.247,22.357 r0 top value=1uF
C18 "SR0603X7R103K1NT95(F)#M123A" 0603 205.75,26.857 r270 top value=0.01uF
C19 "GRM188R71H221KA01D" 0603 209.613,30.037 r0 top value=220pF
C20 "TMK316AB7106KLHT" 1206_180 224.316,61.881 r0 top value=10uF
C21 "06033C104JAT2A" 0603 227.123,65.86 r270 top value=0.1uF
C22 "GRM188R71H221KA01D" 0603 220.452,64.398 r0 top value=220pF
C23 "C4AUJBU4600M18J" FP-C4AUJBU4600M18J_RADIAL-MFG 222.857,17.496 r270 top locked value=6µF
C24 "C4AKOBU4270A3YJ" FP-C4AKOBU4270A3YJ_RADIAL-MFG 263.134,67.406 r90 top locked value=2.7µF
C25 "GRM188R71H221KA01D" 0603 155.201,54.001 r270 top value=220pF
C26 "GRM188R71H221KA01D" 0603 224.855,65.124 r180 top value=220pF
C27 "CGA4J3X7R1E225K125AB" 0805_HV 218.572,59.925 r180 top value=2.2uF
C28 "GRM188R71H221KA01D" 0603 162.89,51.928 r90 top value=220pF
C29 "GRM188R71H221KA01D" 0603 155.203,50.578 r90 top value=220pF
C30 "R533R456050P0M" FP-R533R456050P0M_RADIAL-MFG 22,54.475 r90 top locked value=5.6µF
C31 "06033C104JAT2A" 0603 211.067,39.993 r180 top value=0.1uF
C32 "TMK107BJ105KA-T" 0603 211.067,41.512 r0 top value=1uF
C33 "SR0603X7R103K1NT95(F)#M123A" 0603 206.256,36.064 r0 top value=0.01uF
C34 "TMK316AB7106KLHT" 1206_180 115.917,105.412 r270 top value=10uF
C35 "GRM188R71H221KA01D" 0603 120.793,105.752 r180 top value=220pF
C36 "06033C104JAT2A" 0603 116.508,102.294 r0 top value=0.1uF
C37 "06033C104JAT2A" 0603 133.801,105.949 r270 top value=0.1uF
C38 "TMK107BJ105KA-T" 0603 130.923,105.949 r270 top value=1uF
C39 "GRMJN7R61C206ME05" 0704 150.063,104.617 r270 top value=20uF
C40 "TMK107BBJ106MA-T" 0603 132.264,105.949 r270 top value=10uF
C41 "ZRB18AR61E106ME01L" FP-ZRB18AR61E106ME01L_0603-MFG 129.466,106.38 r90 top value=10µF
C42 "GRM1885C1H331JA01D" 0603 133.876,101.367 r270 top value=330pF
C43 "885012206095" 0603 148.424,104.617 r90 top value=0.1uF
C44 "CGA3E2X7R2A103K080AA" 0603 89.337,103.799 r90 top value=0.01uF
C45 "GRM188R71H221KA01D" 0603 120.031,102.465 r90 top value=220pF
C46 "CGA4J3X7R1E225K125AB" 0805_HV 115.71,110.233 r90 top value=2.2uF
C47 "885012206089" 0603 153.029,101.367 r90 top value=0.01uF
C48 "06033C104JAT2A" 0603 90.187,101.407 r0 top value=0.1uF
C49 "06033C104JAT2A" 0603 77.539,99.722 r0 top value=0.1uF
C50 "885012206095" 0603 142.734,118.704 r0 top value=0.1uF
C51 "885012206095" 0603 136.177,118.521 r180 top value=0.1uF
C52 "06033C104JAT2A" 0603 132.806,129.198 r0 top value=0.1uF
C53 "CGA3E2X7R2A103K080AA" 0603 92.68,63.03 r90 top value=0.01uF
C54 "GRM188R71H221KA01D" 0603 131.936,112.09 r0 top value=220pF
C55 "GRM188R71H221KA01D" 0603 131.936,116.516 r0 top value=220pF
C56 "06033C104JAT2A" 0603 91.439,59.611 r0 top value=0.1uF
C57 "06033C104JAT2A" 0603 77.014,60.97 r180 top value=0.1uF
C58 "GRM188R71H221KA01D" 0603 145.747,114.8 r180 top value=220pF
C59 "TMK316AB7106KLHT" 1206_180 115.693,117.669 r270 top value=10uF
C60 "C4AUJBU4240M1WJ" FP-C4AUJBU4240M1WJ_RADIAL-MFG 89.442,88.73 r180 top locked value=2.4µF
C61 "06033C104JAT2A" 0603 116.468,114.535 r0 top value=0.1uF
C62 "GRM188R71H221KA01D" 0603 119.505,120.62 r270 top value=220pF
C63 "2220Y1K00474KETWS2" 2220 102.113,46.454 r270 top value=0.47uF
C64 "GRM188R71H221KA01D" 0603 119.576,115.952 r90 top value=220pF
C65 "CGA4J3X7R1E225K125AB" 0805_HV 115.797,121.875 r270 top value=2.2uF
C66 "2220Y1K00474KETWS2" 2220 99.231,98.872 r270 top value=0.47uF
C67 "GRM188R71H221KA01D" 0603 170.89,68.155 r0 top value=220pF
C68 "TMK316AB7106KLHT" 1206_180 113.462,56.624 r270 top value=10uF
C69 "GRM188R71H221KA01D" 0603 119.327,58.106 r270 top value=220pF
C70 "06033C104JAT2A" 0603 112.937,52.913 r0 top value=0.1uF
C71 "06033C104JAT2A" 0603 129.147,48.678 r270 top value=0.1uF
C72 "TMK107BJ105KA-T" 0603 125.925,48.457 r270 top value=1uF
C73 "GRMJN7R61C206ME05" 0704 146.672,46.277 r270 top value=20uF
C74 "TMK107BBJ106MA-T" 0603 130.548,48.678 r270 top value=10uF
C75 "ZRB18AR61E106ME01L" FP-ZRB18AR61E106ME01L_0603-MFG 127.391,48.457 r90 top value=10µF
C76 "GRM1885C1H331JA01D" 0603 130.499,42.808 r270 top value=330pF
C77 "885012206095" 0603 145.062,46.31 r90 top value=0.1uF
C78 "GRM188R71H221KA01D" 0603 137.508,71.544 r270 top value=220pF
C79 "GRM188R71H221KA01D" 0603 117.73,53.084 r180 top value=220pF
C80 "CGA4J3X7R1E225K125AB" 0805_HV 112.689,60.913 r90 top value=2.2uF
C81 "885012206089" 0603 145.087,43.207 r90 top value=0.01uF
C82 "GRM188R71H221KA01D" 0603 174.052,68.155 r180 top value=220pF
C83 "GRM188R71H221KA01D" 0603 137.508,68.319 r90 top value=220pF
C84 "885012206095" 0603 139.246,61.925 r90 top value=0.1uF
C85 "885012206095" 0603 132.691,61.2 r180 top value=0.1uF
C86 "GRM188R71H221KA01D" 0603 222.007,73.424 r0 top value=220pF
C87 "GRM188R71H221KA01D" 0603 124.2,131.116 r0 top value=220pF
C88 "GRM188R71H221KA01D" 0603 128.771,55.147 r0 top value=220pF
C89 "GRM188R71H221KA01D" 0603 128.779,59.498 r0 top value=220pF
C90 "GRM188R71H221KA01D" 0603 131.936,113.541 r0 top value=220pF
C91 "GRM188R71H221KA01D" 0603 225.429,73.424 r180 top value=220pF
C92 "GRM188R71H221KA01D" 0603 142.888,56.586 r180 top value=220pF
C93 "TMK316AB7106KLHT" 1206_180 113.062,68.247 r270 top value=10uF
C94 "C4AUJBU4240M1WJ" FP-C4AUJBU4240M1WJ_RADIAL-MFG 89.392,76.082 r180 top locked value=2.4µF
C95 "06033C104JAT2A" 0603 113.787,65.173 r0 top value=0.1uF
C96 "GRM188R71H221KA01D" 0603 119.218,72.163 r180 top value=220pF
C97 "GRM188R71H221KA01D" 0603 127.458,131.118 r180 top value=220pF
C98 "GRM188R71H221KA01D" 0603 117.73,66.849 r180 top value=220pF
C99 "CGA4J3X7R1E225K125AB" 0805_HV 113.121,72.54 r270 top value=2.2uF
C100 "C1812C303KDGLCAUTO" 1812_254 190.358,49.399 r270 top value=0.03uF
C101 "C1812C303KDGLCAUTO" 1812_254 201.862,49.399 r270 top value=0.03uF
C102 "C0603X104K3RACTU" 0603 125.741,34.77 r0 top value=0.1uF
C103 "GRM1885C1H162JA01D" 0603 125.741,27.6 r0 top value=1600pF
C104 "GRM1885C1H162JA01D" 0603 25.708,159.458 r270 top value=1600pF
C105 "GRM1885C1H162JA01D" 0603 119.052,29.82 r90 top value=1600pF
C106 "C1812C303KDGLCAUTO" 1812_254 198.027,49.399 r270 top value=0.03uF
C107 "C1812C303KDGLCAUTO" 1812_254 194.193,49.399 r270 top value=0.03uF
C108 "06033C104JAT2A" 0603 211.247,23.809 r180 top value=0.1uF
C109 "GRM1885C1H162JA01D" 0603 25.708,156.345 r270 top value=1600pF
C110 "C1812C303KDGLCAUTO" 1812_254 244.231,53.474 r270 top value=0.03uF
C111 "C1812C303KDGLCAUTO" 1812_254 240.241,53.474 r270 top value=0.03uF
C112 "GRM188R71H221KA01D" 0603 203.975,39.766 r90 top value=220pF
C113 "C1812C303KDGLCAUTO" 1812_254 252.839,53.474 r270 top value=0.03uF
C115 "UWT1E101MCL1GS" UWT_630x770 117.22,130.992 r270 top value=100uF
C116 "GRM188R71H221KA01D" 0603 162.659,137.417 r180 top value=220pF
C117 "885012206095" 0603 164.453,143.722 r0 top value=0.1uF
C118 "GRM188R71H221KA01D" 0603 165.801,137.383 r0 top value=220pF
C119 "885012206095" 0603 152.677,147.969 r180 top value=0.1uF
C120 "GRM188R71H221KA01D" 0603 152.805,141.619 r180 top value=220pF
C122 "GRM188R71H221KA01D" 0603 156.044,141.65 r0 top value=220pF
C124 "06033C104JAT2A" 0603 170.221,71.681 r270 top value=0.1uF
C125 "06033C104JAT2A" 0603 140.352,71.905 r180 top value=0.1uF
C126 "C1812C303KDGLCAUTO" 1812_254 248.577,53.474 r270 top value=0.03uF
C127 "C1812C303KDGLCAUTO" 1812_254 115.631,46.018 r270 top value=0.03uF
C128 "06033C104JAT2A" 0603 221.282,76.948 r270 top value=0.1uF
C129 "06033C104JAT2A" 0603 123.725,134.453 r270 top value=0.1uF
C130 "C1812C303KDGLCAUTO" 1812_254 119.572,46.026 r270 top value=0.03uF
C131 "C1812C303KDGLCAUTO" 1812_254 111.69,46.018 r270 top value=0.03uF
C132 "C0603X104K3RACTU" 0603 14.586,156.345 r270 top value=0.1uF
C133 "C1812C303KDGLCAUTO" 1812_254 107.749,46.018 r270 top value=0.03uF
C134 "C1812C303KDGLCAUTO" 1812_254 119.711,95.709 r270 top value=0.03uF
C135 "C1812C303KDGLCAUTO" 1812_254 115.847,95.709 r270 top value=0.03uF
C140 "C1812C303KDGLCAUTO" 1812_254 108.12,95.709 r270 top value=0.03uF
C141 "C1812C303KDGLCAUTO" 1812_254 111.996,95.696 r270 top value=0.03uF
C142 "GRM188R71H221KA01D" 0603 147.999,115.541 r90 top value=220pF
C143 "C4AKOBW5140A3JJ" FP-C4AKOBW5140A3JJ_RADIAL-MFG 238.5,99.5 r0 top locked value=14µF
C144 "UWT1E101MCL1GS" UWT_630x770 124.624,143.824 r270 top value=100uF
C146 "06033C104JAT2A" 0603 158.968,54.926 r180 top value=0.1uF
C151 "GRM188R71H221KA01D" 0603 128.771,56.6 r0 top value=220pF
C152 "GRM188R71H221KA01D" 0603 145.468,57.256 r90 top value=220pF
C153 "GRM188R71H221KA01D" 0603 20.928,161.775 r180 top value=220pF
C154 "SR0603X7R103K1NT95(F)#M123A" 0603 15.461,160.447 r0 top value=0.01uF
C155 "C0603X104K3RACTU" 0603 16.108,156.345 r270 top value=0.1uF
C224 "R533R456050P0M" FP-R533R456050P0M_RADIAL-MFG 22,20 r90 top locked value=5.6µF
D1 "C6D20065G" FP-C6D20065G_TO263-2-MFG 192.071,58.053 r270 top
D3 "C6D20065G" FP-C6D20065G_TO263-2-MFG 239.761,62.323 r270 top
D5 "GB02SLT12-214" FP-GB02SLT12-214_DO-214AA-MFG 125.075,113.025 r90 top
D6 "BZT52C16-7-F" SOD-123 128.944,102.375 r270 top value=16V
D8 "GB02SLT12-214" FP-GB02SLT12-214_DO-214AA-MFG 124.721,64.811 r90 top
D9 "BZT52C16-7-F" SOD-123 120.455,61.2 r180 top value=16V
D11 "SMBJ5350B-TP" FP-SMBJ5350B-TP_SMB-MFG 40.794,148.312 r0 top
D12 "ES1C-13-F" SMA 47.794,148.312 r180 top value=150V
D13 "150060VS75000" WL-SMCW_GREEN 48.211,161.342 r90 top value=Green
D14 "KG DELLS1.22-JGKH-24" "FP-KG DELLS1.22-JGKH-24_0603-MFG" 45.575,151.5 r0 top
D15 "150060VS75000" WL-SMCW_GREEN 51.177,161.342 r90 top value=Green
D16 "150060VS75000" WL-SMCW_GREEN 54.142,161.342 r90 top value=Green
D17 "KG DELLS1.22-JGKH-24" "FP-KG DELLS1.22-JGKH-24_0603-MFG" 170.276,56.159 r180 top
D18 "KG DELLS1.22-JGKH-24" "FP-KG DELLS1.22-JGKH-24_0603-MFG" 218.902,57.253 r270 top
D19 "KG DELLS1.22-JGKH-24" "FP-KG DELLS1.22-JGKH-24_0603-MFG" 117.879,108.426 r0 top
D20 "KG DELLS1.22-JGKH-24" "FP-KG DELLS1.22-JGKH-24_0603-MFG" 114.052,124.702 r90 top
D21 "KG DELLS1.22-JGKH-24" "FP-KG DELLS1.22-JGKH-24_0603-MFG" 115.559,59.379 r0 top
D22 "KG DELLS1.22-JGKH-24" "FP-KG DELLS1.22-JGKH-24_0603-MFG" 116.254,73.885 r0 top
FB1 "MH1608-601Y" FP-MH1608-601Y_0603-MFG 211.732,25.384 r180 top
FB2 "MH1608-601Y" FP-MH1608-601Y_0603-MFG 210.88,43.108 r180 top
FB3 "MH1608-601Y" FP-MH1608-601Y_0603-MFG 125.775,36.175 r0 top
FB4 "MH1608-601Y" FP-MH1608-601Y_0603-MFG 151.772,104.6 r270 top
FB5 "MH1608-601Y" FP-MH1608-601Y_0603-MFG 89.815,99.847 r180 top
FB6 "MH1608-601Y" FP-MH1608-601Y_0603-MFG 148.712,45.51 r180 top
FB9 "MH1608-601Y" FP-MH1608-601Y_0603-MFG 142.119,120.244 r180 top
FB10 "MH1608-601Y" FP-MH1608-601Y_0603-MFG 140.639,61.675 r270 top
FB11 "MH1608-601Y" FP-MH1608-601Y_0603-MFG 14.986,154.004 r0 top
FB12 "MH1608-601Y" FP-MH1608-601Y_0603-MFG 77.519,97.971 r180 top
FB13 "MH1608-601Y" FP-MH1608-601Y_0603-MFG 78.693,59.23 r180 top
FB14 "MH1608-601Y" FP-MH1608-601Y_0603-MFG 91.366,57.973 r180 top
FID1 "Fiducial" Fiducial10-20 273.135,99 r180 top
FID2 "Fiducial" Fiducial10-20 255,4.73 r180 top
FID3 "Fiducial" Fiducial10-20 2.107,18 r180 top
FID4 "Fiducial" Fiducial10-20 4.793,150 r90 bottom
FID5 "Fiducial" Fiducial10-20 10.281,58.338 r90 bottom
FID6 "Fiducial" Fiducial10-20 250,5.035 r90 bottom
J1 "796636-3" FP-796636-3_HDR3-MFG 195.4,102.95 r0 top locked
J2 "1714955" Phoenix_1714955 8.418,49.204 r270 top
J3 "1714955" Phoenix_1714955 8.418,29.302 r270 top
J4 "1714955" Phoenix_1714955 8.418,97.998 r270 top
J5 "1714955" Phoenix_1714955 8.418,83.857 r270 top
J6 "SHF-112-01-L-D-TH" FP-SHF-112-01-L-D-TH_HDR24-MFG 121,156.276 r180 top locked
J8 "SHF-112-01-L-D-TH" FP-SHF-112-01-L-D-TH_HDR24-MFG 145,156.276 r180 top locked
K1 "G7L-2A-X DC12" "FP-G7L-2A-X DC12_PTH_RELAY_52MM5_35MM5-MFG" 29,127 r0 top locked
L1 "B180974" FP-B180974_PTH12_41MM5_40MM5-MFG 178.11,23.6 r270 top locked value=160uH
L2 "SDEM20161T-4R7MS" FP-SDEM20161T-4R7MS_SMD2-MFG 172.425,58.309 r270 top
L3 "SRP1038A-1R0M" SRP1038A 209.944,95.348 r180 top value=1uH
L4 "B180974" FP-B180974_PTH12_41MM5_40MM5-MFG 253.003,30 r0 top locked value=160uH
L5 "SDEM20161T-4R7MS" FP-SDEM20161T-4R7MS_SMD2-MFG 217.616,62.067 r0 top
L6 "SRP2313AA-220M" SRP2313AA 42,43 r270 top value=22uH
L7 "SDEM20161T-4R7MS" FP-SDEM20161T-4R7MS_SMD2-MFG 119.048,110.383 r270 top
L8 "SRP2313AA-220M" SRP2313AA 42.084,14 r270 top value=22uH
L9 "B180975" FP-B180975_PTH12_55MM5_50MM0-MFG 81,137 r90 top locked value=186.7uH
L10 "SDEM20161T-4R7MS" FP-SDEM20161T-4R7MS_SMD2-MFG 118.611,123.501 r270 top
L11 "SDEM20161T-4R7MS" FP-SDEM20161T-4R7MS_SMD2-MFG 116.968,61.715 r270 top
L13 "B180975" FP-B180975_PTH12_55MM5_50MM0-MFG 79,28.058 r270 top locked value=186.7uH
L14 "SDEM20161T-4R7MS" FP-SDEM20161T-4R7MS_SMD2-MFG 116.198,71.89 r90 top
L18 "B180986" FP-B180986_PTH12-MFG 51.475,78.111 r270 top locked value=22uH
LBL1 "THT-14-423-10" Label_650x200 169.331,83.944 r0 top
LOGO1 "CAUTION HOT SURFACE" IEC_HotSurface_Small 114.784,16 r0 top
Logo2 "CE Mark" CE_Mark_5mm 187.242,84.404 r0 top
Logo3 "FCC disclaimer" FCC_disclaimer 177.531,90.575 r0 top
Logo4 "WEEE logo" WEEE_Minimum 195.76,85.953 r0 top
LOGO5 "DANGER HIGH VOLTAGE" IEC_HighVoltage_Small 168.326,102.917 r0 top
MP1 "9774015960R" FP-9774015960R_ROUND_SPACER_6MM0-MFG 115.184,4.869 r180 bottom
MP2 "9774015960R" FP-9774015960R_ROUND_SPACER_6MM0-MFG 211.343,110.123 r180 bottom locked
MP3 "9774015960R" FP-9774015960R_ROUND_SPACER_6MM0-MFG 164.985,160.017 r180 bottom locked
MP4 "9774015960R" FP-9774015960R_ROUND_SPACER_6MM0-MFG 5.017,160.089 r180 bottom locked
MP5 "9774015960R" FP-9774015960R_ROUND_SPACER_6MM0-MFG 4.972,4.96 r180 bottom locked
MP6 "9774015960R" FP-9774015960R_ROUND_SPACER_6MM0-MFG 269.981,5.035 r180 bottom locked
MP7 "9774015960R" FP-9774015960R_ROUND_SPACER_6MM0-MFG 270,110 r180 bottom locked
MP8 "9774015960R" FP-9774015960R_ROUND_SPACER_6MM0-MFG 111.277,141.653 r180 bottom
MP9 "9774015960R" FP-9774015960R_ROUND_SPACER_6MM0-MFG 5,67.046 r180 bottom locked
Q1 "CSD17318Q2" FP-CSD17318Q2_WSON6-MFG 40.844,153.416 r180 top
R1 "RG1608P-560-B-T5" 0603 173.776,61.695 r0 top value=56
R2 "PTCEL13R102SBE" FP-PTCEL13R102SBE_RADIAL-MFG 56.475,104.443 r0 top value=1000Ω
R3 "RG1608P-560-B-T5" 0603 139.372,129.998 r90 top value=56
R4 "RG1608P-560-B-T5" 0603 132.411,134.417 r0 top value=56
R5 "RG1608P-560-B-T5" 0603 139.37,133.261 r270 top value=56
R6 "RC0603FR-0720KL" 0603 177.151,61.94 r180 top value=20.0k
R7 "RT0603DRE071K67L" 0603 48.807,151.41 r180 top value=1.67k
R8 "RG1608P-560-B-T5" 0603 212.207,29.24 r90 top value=56
R9 "RT0603BRD0710RL" 0603 203.304,27.69 r0 top value=10.0
R10 "RT0603BRD0710RL" 0603 203.304,25.982 r0 top value=10.0
R11 "RG1608P-560-B-T5" 0603 220.465,65.873 r0 top value=56
R12 "RG1608P-103-B-T5" 0603 17.658,163.25 r0 top value=10.0k
R13 "RG1608P-560-B-T5" 0603 151.968,54.001 r270 top value=56
R14 "RG1608P-560-B-T5" 0603 161.328,51.928 r90 top value=56
R15 "RG1608P-560-B-T5" 0603 151.97,50.578 r90 top value=56
R16 "RC0603FR-0720KL" 0603 224.855,66.673 r180 top value=20.0k
R17 "CSS2H-2512K-3L00F" FP-CSS2H-2512K-3L00F_2512-MFG 179.842,35.683 r90 bottom value=3m
R18 "CSS2H-2512K-3L00F" FP-CSS2H-2512K-3L00F_2512-MFG 223.767,40.763 r90 bottom value=3m
R19 "RG1608P-560-B-T5" 0603 206.7,41.623 r180 top value=56
R20 "RT0603BRD0710RL" 0603 206.256,34.593 r180 top value=10.0
R21 "RT0603DRE072RL" 0603 125.37,118.437 r270 top value=2.00
R22 "ERJ-3EKF1202V" 0603 149.616,101.013 r180 top value=12.0k
R23 "RT0603DRE0738K8L" 0603 133.076,103.629 r0 top value=38.8k
R24 "RG1608P-560-B-T5" 0603 120.793,107.167 r180 top value=56
R25 "ERJ-3EKF1202V" 0603 153.261,104.637 r270 top value=12.0k
R26 "RG1608P-560-B-T5" 0603 15.461,158.983 r180 top value=56
R27 "RT0603BRD074K02L" 0603 154.787,104.617 r270 top value=4.02k
R28 "TNPV1206680KBEEN" TNPV1206 112.693,24.748 r90 top value=680k
R29 "RG1608P-103-B-T5" 0603 132.287,101.367 r270 top value=10.0k
R30 "TNPV1206680KBEEN" TNPV1206 112.766,29.35 r90 top value=680k
R31 "TNPV1206680KBEEN" TNPV1206 115.31,32.805 r0 top value=680k
R32 "RC0603FR-0720KL" 0603 121.523,102.465 r90 top value=20.0k
R33 "TNPV1206680KBEEN" TNPV1206 137.047,32.341 r180 top value=680k
R34 "RG1608P-560-B-T5" 0603 131.936,117.89 r180 top value=56
R35 "RG1608P-560-B-T5" 0603 131.936,114.981 r180 top value=56
R36 "TNPV1206680KBEEN" TNPV1206 133.775,30.295 r270 top value=680k
R37 "RG1608P-560-B-T5" 0603 145.759,113.261 r180 top value=56
R38 "RG1608P-560-B-T5" 0603 131.936,109.118 r180 top value=56
R39 "RG1608P-103-B-T5" 0603 137.741,129.998 r90 top value=10.0k
R40 "RG1608P-560-B-T5" 0603 121.011,120.62 r270 top value=56
R41 "RG1608P-103-B-T5" 0603 17.658,161.85 r180 top value=10.0k
R42 "TNPV1206680KBEEN" TNPV1206 130.175,28.475 r180 top value=680k
R43 "TNPV1206680KBEEN" TNPV1206 17.011,148.075 r90 top value=680k
R44 "TNPV1206680KBEEN" TNPV1206 21.017,149.042 r0 top value=680k
R45 "RC0603FR-0720KL" 0603 121.085,115.952 r90 top value=20.0k
R46 "RT0603DRE072RL" 0603 126.009,70.579 r270 top value=2.00
R47 "ERJ-3EKF1202V" 0603 145.887,40.569 r180 top value=12.0k
R48 "RT0603DRE0738K8L" 0603 129.712,45.197 r0 top value=38.8k
R49 "RG1608P-560-B-T5" 0603 120.929,58.106 r270 top value=56
R50 "ERJ-3EKF1202V" 0603 149.187,44.082 r180 top value=12.0k
R51 "RG1608P-560-B-T5" 0603 145.734,116.296 r180 top value=56
R52 "RT0603BRD074K02L" 0603 146.672,43.207 r90 top value=4.02k
R53 "TNPV1206680KBEEN" TNPV1206 22.617,152.923 r90 top value=680k
R54 "RG1608P-103-B-T5" 0603 128.899,42.833 r270 top value=10.0k
R55 "RCS06030000Z0EA" 0603 121.957,151.274 r90 top value=0
R56 "RT0603BRD0710RL" 0603 91.449,104.634 r180 top value=10.0
R57 "RC0603FR-0720KL" 0603 117.73,54.582 r180 top value=20.0k
R58 "RT0603BRD0710RL" 0603 91.449,102.944 r180 top value=10.0
R59 "RG1608P-560-B-T5" 0603 128.779,60.99 r180 top value=56
R60 "RG1608P-560-B-T5" 0603 128.782,58.054 r180 top value=56
R61 "RC0603FR-0756RL" 0603 73.358,104.539 r0 top value=56.0
R62 "RG1608P-560-B-T5" 0603 142.888,55.119 r180 top value=56
R63 "RG1608P-560-B-T5" 0603 128.779,52.144 r180 top value=56
R64 "RG1608P-103-B-T5" 0603 137.739,133.26 r270 top value=10.0k
R65 "RG1608P-560-B-T5" 0603 119.218,70.661 r180 top value=56
R66 "RC0603FR-0756RL" 0603 73.339,102.964 r0 top value=56.0
R67 "RT0603BRD0710RL" 0603 95.553,61.322 r90 top value=10.0
R68 "TNPV1206680KBEEN" TNPV1206 33,148.075 r90 top value=680k
R69 "TNPV1206680KBEEN" TNPV1206 33,153.091 r90 top value=680k
R70 "RC0603FR-0720KL" 0603 117.73,68.319 r180 top value=20.0k
R71 "RT0603BRD0710RL" 0603 209.356,36.083 r180 top value=10.0
R72 "RG1608P-560-B-T5" 0603 211.067,38.564 r0 top value=56
R73 "RC0603FR-0756RL" 0603 76.467,64.27 r0 top value=56.0
R74 "TNPV1206680KBEEN" TNPV1206 30.841,156.582 r180 top value=680k
R75 "RG1608P-560-B-T5" 0603 170.89,65.009 r0 top value=56
R76 "RG1608P-560-B-T5" 0603 134.508,71.544 r270 top value=56
R77 "RG1608P-560-B-T5" 0603 174.052,65.009 r180 top value=56
R78 "RG1608P-560-B-T5" 0603 134.508,68.319 r90 top value=56
R79 "RG1608P-103-B-T5" 0603 170.89,66.509 r0 top value=10.0k
R80 "RG1608P-103-B-T5" 0603 136.008,71.544 r270 top value=10.0k
R81 "RG1608P-103-B-T5" 0603 174.052,66.509 r180 top value=10.0k
R82 "RG1608P-103-B-T5" 0603 136.008,68.319 r90 top value=10.0k
R83 "RG1608P-560-B-T5" 0603 222.007,70.424 r0 top value=56
R84 "RG1608P-560-B-T5" 0603 124.2,127.887 r0 top value=56
R85 "RG1608P-560-B-T5" 0603 225.429,70.424 r180 top value=56
R86 "RG1608P-560-B-T5" 0603 121.761,34.695 r0 top value=56
R87 "RG1608P-560-B-T5" 0603 128.371,34.355 r90 top value=56
R88 "PTCEL13R102SBE" FP-PTCEL13R102SBE_RADIAL-MFG 37.91,104.337 r0 top value=1000Ω
R89 "RG1608P-560-B-T5" 0603 127.458,127.888 r180 top value=56
R90 "RG1608P-103-B-T5" 0603 222.007,71.804 r0 top value=10.0k
R91 "RG1608P-103-B-T5" 0603 124.2,129.518 r0 top value=10.0k
R92 "RG1608P-103-B-T5" 0603 225.429,71.804 r180 top value=10.0k
R93 "RG1608P-103-B-T5" 0603 127.458,129.52 r180 top value=10.0k
R94 "CSR0805FKR250" FP-CSR0805FKR250_0805-MFG 105.282,50.74 r0 top
R95 "RC0603FR-0756RL" 0603 76.467,62.8 r0 top value=56.0
R96 "RT0603BRD0710RL" 0603 94.12,61.322 r90 top value=10.0
R97 "RCS06030000Z0EA" 0603 119.038,151.274 r90 top value=0
R98 "CSR0805FKR250" FP-CSR0805FKR250_0805-MFG 104.464,101.472 r0 top
R105 "RC0603JR-075K6L" 0603 168.131,57.256 r270 top value=5.6k
R106 "RG1608P-103-B-T5" 0603 125.741,26.125 r180 top value=10.0k
R107 "RC0603FR-0710RL" 0603 125.73,24.571 r180 top value=10.0
R108 "RC0603FR-0780R6L" 0603 161.56,142.733 r90 top value=80.6
R109 "RC0603FR-0780R6L" 0603 161.859,133.58 r90 top value=80.6
R111 "RC0603FR-0710RL" 0603 117.279,26.094 r90 top value=10.0
R112 "RC0603FR-0780R6L" 0603 166.665,133.648 r90 top value=80.6
R113 "RC0603FR-0780R6L" 0603 166.92,142.733 r90 top value=80.6
R116 "RC0603FR-0780R6L" 0603 150.082,147.169 r90 top value=80.6
R117 "RC0603FR-0780R6L" 0603 150.557,140.85 r270 top value=80.6
R120 "RC0603FR-0780R6L" 0603 156.908,137.922 r90 top value=80.6
R121 "RC0603FR-0780R6L" 0603 155.244,148.869 r90 top value=80.6
R125 "RG1608P-103-B-T5" 0603 156.044,140.158 r0 top value=10.0k
R127 "RG1608P-103-B-T5" 0603 152.805,140.158 r180 top value=10.0k
R129 "RG1608P-103-B-T5" 0603 165.801,135.919 r0 top value=10.0k
R131 "RG1608P-103-B-T5" 0603 162.659,135.914 r180 top value=10.0k
R132 "RC0603JR-075K6L" 0603 217.328,57.32 r270 top value=5.6k
R133 "RC0603JR-075K6L" 0603 120.953,110.29 r270 top value=5.6k
R134 "CSS2H-2512R-1L00F" CSS2H-2512_H077Y042 99.505,109.56 r0 bottom value=0.001
R135 "RC0603JR-075K6L" 0603 116.395,125.597 r180 top value=5.6k
R136 "RC0603JR-075K6L" 0603 117.369,59.023 r90 top value=5.6k
R137 "CSS2H-2512R-1L00F" CSS2H-2512_H077Y042 95.725,54.286 r0 bottom value=0.001
R138 "RC0603JR-075K6L" 0603 119.169,74.255 r180 top value=5.6k
R139 "RG1608P-103-B-T5" 0603 27.206,159.458 r90 top value=10.0k
R140 "RG1608P-103-B-T5" 0603 117.294,29.82 r90 top value=10.0k
R141 "RG1608P-103-B-T5" 0603 27.206,156.345 r270 top value=10.0k
R144 "RG1608P-560-B-T5" 0603 43.266,155.091 r270 top value=56
R145 "RG1608P-103-B-T5" 0603 40.844,157.194 r180 top value=10.0k
R146 "RG1608P-560-B-T5" 0603 207.806,23.809 r180 top value=56
R147 "RT0603DRE071K67L" 0603 48.211,157.575 r90 top value=1.67k
R148 "RC1206FR-072R2L" 1206 139.211,149.733 r90 top value=2.20
R149 "RG1608P-560-B-T5" 0603 123.311,26.85 r270 top value=56
R150 "RG1608P-560-B-T5" 0603 26.433,161.785 r0 top value=56
R151 "RG1608P-560-B-T5" 0603 120.211,27.325 r0 top value=56
R152 "RG1608P-560-B-T5" 0603 26.481,153.977 r0 top value=56
R153 "CRCW0603499RFKEAC" 0603 51.177,157.575 r90 top value=499
R154 "RT0603DRE07218RL" 0603 54.142,157.575 r90 top value=218
R155 "RG1608P-560-B-T5" 0603 131.936,110.59 r180 top value=56
R156 "RG1608P-103-B-T5" 0603 153.585,54.001 r270 top value=10.0k
R157 "RG1608P-103-B-T5" 0603 153.586,50.578 r90 top value=10.0k
R158 "RG1608P-560-B-T5" 0603 128.775,53.673 r180 top value=56
R159 "RG1608P-560-B-T5" 0603 142.888,58.054 r180 top value=56
R160 "RC1206FR-072R2L" 1206 141.586,149.733 r90 top value=2.20
R161 "RC1206FR-072R2L" 1206 144.064,149.733 r90 top value=2.20
R162 "RC1206FR-072R2L" 1206 146.647,149.733 r90 top value=2.20
R163 "RC1206FR-072R2L" 1206 158.581,148.069 r90 top value=2.20
R164 "RC1206FR-072R2L" 1206 160.934,148.069 r90 top value=2.20
R165 "RC1206FR-072R2L" 1206 163.434,148.069 r90 top value=2.20
R166 "RC1206FR-072R2L" 1206 165.934,148.069 r90 top value=2.20
TP1 "5001" Keystone5001 154.455,136.724 r0 top
TP2 "5001" Keystone5001 158.059,58.87 r90 top
TP3 "5001" Keystone5001 125.778,102.875 r90 top
TP4 "5001" Keystone5001 128.499,68.465 r90 top
TP5 "5001" Keystone5001 147.683,52.981 r180 top
TP6 "5001" Keystone5001 126.362,44.141 r180 top
TP7 "TP_SM_1MM" TP_SM_1MM 87.531,99.847 r90 top
TP8 "TP_SM_1MM" TP_SM_1MM 89.131,58.41 r90 top
TP9 "S2751-46R" Harwin_S2751-46R 104.733,105.628 r90 top
TP10 "S2751-46R" Harwin_S2751-46R 102.012,56.212 r270 top
TP12 "S2751-46R" Harwin_S2751-46R 184.041,49.44 r180 top
TP13 "5001" Keystone5001 209.788,54.812 r90 top
TP14 "5001" Keystone5001 211.6,32.777 r90 top
TP15 "5001" Keystone5001 203.447,22.765 r90 top
TP16 "S2751-46R" Harwin_S2751-46R 231.857,53.643 r180 top
TP17 "5001" Keystone5001 266.598,89 r90 top
TP18 "5001" Keystone5001 211.384,45.887 r90 top
TP19 "5001" Keystone5001 202.338,36.083 r90 top
TP20 "5001" Keystone5001 74.339,107.2 r90 top
TP21 "5001" Keystone5001 74.333,100.18 r90 top
TP22 "5001" Keystone5001 124.401,125.097 r90 top
TP23 "5001" Keystone5001 78.982,67.579 r90 top
TP24 "5001" Keystone5001 76.033,57.995 r90 top
TP27 "5001" Keystone5001 135.427,37.169 r90 top
TP28 "5001" Keystone5001 30.88,161.766 r90 top
TP29 "5001" Keystone5001 118.478,35.233 r90 top
TP30 "5001" Keystone5001 123.218,38.593 r90 top
TP31 "5001" Keystone5001 130.629,37.014 r90 top
TP32 "5001" Keystone5001 28.918,149.589 r90 top
TP33 "5001" Keystone5001 18.552,153.231 r90 top
TP34 "5001" Keystone5001 110.543,131.622 r90 top
TP35 "5001" Keystone5001 203.911,30.79 r90 top
TP36 "5001" Keystone5001 37.125,160.335 r90 top
TP37 "5001" Keystone5001 164.28,132.169 r90 top
TP38 "5001" Keystone5001 130.925,33.459 r90 top
TP39 "5001" Keystone5001 3.247,58 r90 top
TP40 "5001" Keystone5001 192,96.477 r90 top
TP41 "5001" Keystone5001 11.151,40.987 r90 top
TP42 "5001" Keystone5001 206.667,102.791 r90 top
TP43 "5001" Keystone5001 2.607,38.725 r90 top
TP44 "5001" Keystone5001 7.836,20.05 r90 top
TP45 "5001" Keystone5001 8.006,106.974 r90 top
TP46 "5001" Keystone5001 8.418,75.521 r90 top
U1 "LMG3522R030-Q1" RQS0052C-C01-MFG 178.316,51.734 r180 bottom
U2 "SN74LVC2G34DBVR" DBV0006A_N 164.251,140.633 r90 top
U3 "INA181A2IDBV" DBV0006A_N 208.707,27.059 r270 top
U4 "LMG3522R030-Q1" RQS0052C-C01-MFG 225.807,56.31 r180 bottom
U5 "INA181A2IDBV" DBV0006A_N 207.256,38.766 r0 top
U6 "UCC14131QDWNRQ1" DWJ0036A-MFG 141.42,105.592 r180 top
U7 "LMG3522R030-Q1" RQS0052C-C01-MFG 110.783,103.579 r90 bottom
U8 "SN74LVC1G08DBVT" DBV0005A_N 132.989,131.785 r180 top
U9 "ISO7741DBQR" DBQ0016A_N 139.177,114.975 r0 top
U10 "LMG3522R030-Q1" RQS0052C-C01-MFG 110.783,117.1 r90 bottom
U11 "UCC14131QDWNRQ1" DWJ0036A-MFG 137.887,47.645 r180 top
U12 "LMG3522R030-Q1" RQS0052C-C01-MFG 107.737,54.374 r90 bottom
U13 "SN74LVC1G08DBVT" DBV0005A_N 158.355,52.078 r0 top
U14 "ISO7741DBQR" DBQ0016A_N 136.391,57.495 r0 top
U15 "LMG3522R030-Q1" RQS0052C-C01-MFG 107.737,67.691 r90 bottom
U16 "OPA2388IDR" D0008A-MFG 123.751,31.24 r0 top
U17 "SN74LVC1G08DBVT" DBV0005A_N 172.885,71.303 r90 top
U18 "SN74LVC1G08DBVT" DBV0005A_N 140.376,68.563 r0 top
U19 "SN74LVC1G08DBVT" DBV0005A_N 224.262,76.448 r90 top
U20 "SN74LVC1G08DBVT" DBV0005A_N 126.508,134.27 r90 top
U21 "AMC1302DWV" DWV0008A 81.97,103.799 r180 top
U22 "AMC1302DWV" DWV0008A 85.189,63.075 r180 top
U23 "OPA2388IDR" D0008A-MFG 20.928,158.25 r180 top
U25 "SN74LVC2G34DBVR" DBV0006A_N 152.98,144.961 r90 top
ZZ1 "This Assembly Note is for PCB labels only" AssemblyNoteLabel 290.747,96.5 r0 top
ZZ2 "These assemblies are ESD sensitive, ESD precautions shall be observed." AssemblyNote 290.239,100.5 r0 top
ZZ3 "These assemblies must be clean and free from flux and all contaminants. Use of no clean flux is not acceptable." AssemblyNote 290.5,104.5 r0 top
ZZ4 "These assemblies must comply with workmanship standards IPC-A-610 Class 2, unless otherwise specified." AssemblyNote 290.5,108 r0 top

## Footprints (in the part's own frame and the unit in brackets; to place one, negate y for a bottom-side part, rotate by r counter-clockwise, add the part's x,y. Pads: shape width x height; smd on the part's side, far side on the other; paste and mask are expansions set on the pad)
0603 [mm] "0603 from SM-752 data"
  rect 1x0.95 smd: 1(-0.8,0) 2(0.8,0)
  silkscreen extent -1.52,-0.69 1.52,0.69, body extent -0.87,-0.47 0.87,0.47, height 1
0704 [mm] "Murata"
  rrect11% 1x1.2 smd: 1(-0.9,0) 2(0.9,0)
  silkscreen extent -0.25,-0.77 0.25,0.8, body extent -0.95,-0.55 0.95,0.55, height 0.8
0805_HV [mil] "0805 with 30mil clearance between pads"
  rect 50x63 smd: 1(-40,0) 2(40,0)
  silkscreen extent -74,-40 74,40, body extent -43,-29 43,29, height 57
1206 [mm] "1206 from SM-752 data"
  rect 1.3x1.85 smd: 1(-1.45,0) 2(1.45,0)
  silkscreen extent -2.4,-1.21 2.4,1.21, body extent -1.7,-0.9 1.7,0.9, height 1.35
1206_180 [mm] "1206_180"
  rect 1.1x1.6 smd: 1(-1.7,0) 2(1.7,0)
  silkscreen extent -0.9,-1 0.9,1, body extent -1.75,-0.95 1.75,0.95, height 1.8
1812_254 [mm] "SMD, 2-Leads, Body 4.8x3.4mm"
  rect 1.6x3.4 smd: 1(-2,0) 2(2,0)
  silkscreen extent -0.8,-1.7 0.8,1.7, body extent -2.4,-1.7 2.4,1.7, height 2.54
2220 [mm] "Chip Capacitor, Body 5.7x5.0mm, IPC Medium Density"
  rect 1.6x5.3 smd: 1(-2.6,0) 2(2.6,0)
  silkscreen extent -3.69,-2.94 3.69,2.94, body extent -2.95,-2.62 2.95,2.62, height 1.35
AssemblyNote [mm] "Assembly Note"
AssemblyNoteLabel [mm] "Assembly Note for PCB Labels"
CE_Mark_5mm [mm] "Minimum text height for CE Mark"
  silkscreen extent -3.5,-2.5 3.5,2.5
CSS2H-2512_H077Y042 [mm] "SMD, 2-Leads, Body 6.35x3.05mm"
  rrect6% 1.8x3.4 smd: 1(-2.6,0) 2(2.6,0)
  body extent -3.18,-1.53 3.17,1.52, height 0.83
D0008A-MFG [mm]
  rrect17% 1.55x0.6 smd paste+0 mask+0: 1(-2.7,1.905) 2(-2.7,0.635) 3(-2.7,-0.635) 4(-2.7,-1.905) 5(2.7,-1.905) 6(2.7,-0.635) 7(2.7,0.635) 8(2.7,1.905)
  silkscreen extent -4.17,-2.5 1.5,2.5, body extent -3.57,-2.75 3.57,2.75, height 0.25
DBQ0016A_N [mm] "SOP, 16-Leads, Body 4.9x3.9mm, Pitch 0.635mm, IPC Medium Density"
  oval 1.45x0.4 smd: 1(-2.725,2.222) 2(-2.725,1.587) 3(-2.725,0.953) 4(-2.725,0.318) 5(-2.725,-0.318) 6(-2.725,-0.953) 7(-2.725,-1.587) 8(-2.725,-2.222) 9(2.725,-2.222) 10(2.725,-1.587) 11(2.725,-0.953) 12(2.725,-0.318) 13(2.725,0.318) 14(2.725,0.953) 15(2.725,1.587) 16(2.725,2.222)
  silkscreen extent -3.35,-2.5 1.1,2.68, body extent -3.01,-2.45 3.01,2.45, height 1.63
DBV0005A_N [mm] "SOT23, 5-Leads, Body 2.9x1.6mm, Pitch 0.95mm, Lead Span 2.8mm, IPC Medium Density"
  rrect17% 1x0.6 smd: 1(-1.375,0.95) 2(-1.375,0) 3(-1.375,-0.95) 4(1.375,-0.95) 5(1.375,0.95)
  silkscreen extent -0.25,-1.55 0.25,1.55, body extent -1.42,-1.46 1.42,1.46, height 1.09
DBV0006A_N [mm] "SOT23, 6-Leads, Body 2.9x1.6mm, Pitch 0.95mm, Lead Span 2.8mm, IPC Medium Density"
  rrect17% 1x0.6 smd: 1(-1.375,0.95) 2(-1.375,0) 3(-1.375,-0.95) 4(1.375,-0.95) 5(1.375,0) 6(1.375,0.95)
  silkscreen extent -1.68,-1.55 0.5,1.55, body extent -1.42,-1.46 1.42,1.46, height 1.12
DWJ0036A-MFG [mm]
  rrect22% 1.85x0.45 smd paste+0 mask+0: 1(-4.975,5.525) 2(-4.975,4.875) 3(-4.975,4.225) 4(-4.975,3.575) 5(-4.975,2.925) 6(-4.975,2.275) 7(-4.975,1.625) 8(-4.975,0.975) 9(-4.975,0.325) 10(-4.975,-0.325) 11(-4.975,-0.975) 12(-4.975,-1.625) 13(-4.975,-2.275) 14(-4.975,-2.925) 15(-4.975,-3.575) 16(-4.975,-4.225) 17(-4.975,-4.875) 18(-4.975,-5.525) 19(4.975,-5.525) 20(4.975,-4.875) 21(4.975,-4.225) 22(4.975,-3.575) 23(4.975,-2.925) 24(4.975,-2.275) 25(4.975,-1.625) 26(4.975,-0.975) 27(4.975,-0.325) 28(4.975,0.325) 29(4.975,0.975) 30(4.975,1.625) 31(4.975,2.275) 32(4.975,2.925) 33(4.975,3.575) 34(4.975,4.225) 35(4.975,4.875) 36(4.975,5.525)
  silkscreen extent -6.58,-6.47 3.8,6.47, body extent -5.15,-6.42 5.15,6.42, height 3.55
DWV0008A [mm] "SOIC, 8-Leads, Body 5.95x7.6mm (max), Pitch 1.27mm"
  rrect17% 1.8x0.6 smd: 1(-5.45,1.905) 2(-5.45,0.635) 3(-5.45,-0.635) 4(-5.45,-1.905) 5(5.45,-1.905) 6(5.45,-0.635) 7(5.45,0.635) 8(5.45,1.905)
  silkscreen extent -6.25,-2.95 2.98,2.95, body extent -5.77,-2.92 5.77,2.93, height 2.67
FCC_disclaimer [mm]
Fiducial10-20 [mm]
  round 1 smd mask+0.5: 1(0,0)
  Top Layer keep-out circle w1.178: c0,0 r0.5
FP-796636-3_HDR3-MFG [mm]
  rrect5% 2.15x2.15 hole 1.4 paste-1000 mask+0: 1(-4.83,-0.325)
  round 2.15 hole 1.4 paste-1000 mask+0: 2(0.25,-0.325) 3(5.33,-0.325)
  silkscreen extent -8.78,-4.87 8.78,4.25, body extent -8.88,-4.35 8.88,4.35, height 0.25
FP-9774015960R_ROUND_SPACER_6MM0-MFG [mm]
  round 5.245 smd paste-1000 mask-1000: 1(0,0)
  round 4.4 hole 4.4 unplated paste-1000 mask+0: ""(0,0)
  Top Layer circle w1.5: c0,0 r2.95
  silkscreen extent -4.15,-4.15 4.15,4.15, body extent -3,-3 3,3, height 1.6
FP-B180974_PTH12_41MM5_40MM5-MFG [mm]
  rrect5% 2.2x2.2 hole 1.5 paste-1000 mask+0: 1(-17.5,15)
  round 2.2 hole 1.5 paste-1000 mask+0: 2(-17.5,10) 3(-17.5,5) 4(-17.5,-5) 5(-17.5,-10) 6(-17.5,-15) 7(17.5,-15) 8(17.5,-10) 9(17.5,-5) 10(17.5,5) 11(17.5,10) 12(17.5,15)
  silkscreen extent -21.47,-20.25 20.75,20.25, body extent -20.85,-20.35 20.85,20.35, height 0.25
FP-B180975_PTH12_55MM5_50MM0-MFG [mm]
  rrect5% 2.2x2.2 hole 1.5 paste-1000 mask+0: 1(-21.9,15)
  round 2.2 hole 1.5 paste-1000 mask+0: 2(-21.9,10) 3(-21.9,5) 4(-21.9,-5) 5(-21.9,-10) 6(-21.9,-15) 7(21.9,-15) 8(21.9,-10) 9(21.9,-5) 10(21.9,5) 11(21.9,10) 12(21.9,15)
  silkscreen extent -28.47,-25 27.75,25, body extent -27.85,-25.1 27.85,25.1, height 0.25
